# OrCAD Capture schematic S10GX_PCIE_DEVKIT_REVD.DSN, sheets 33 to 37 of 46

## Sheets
33 Power - Select Power Input: size C
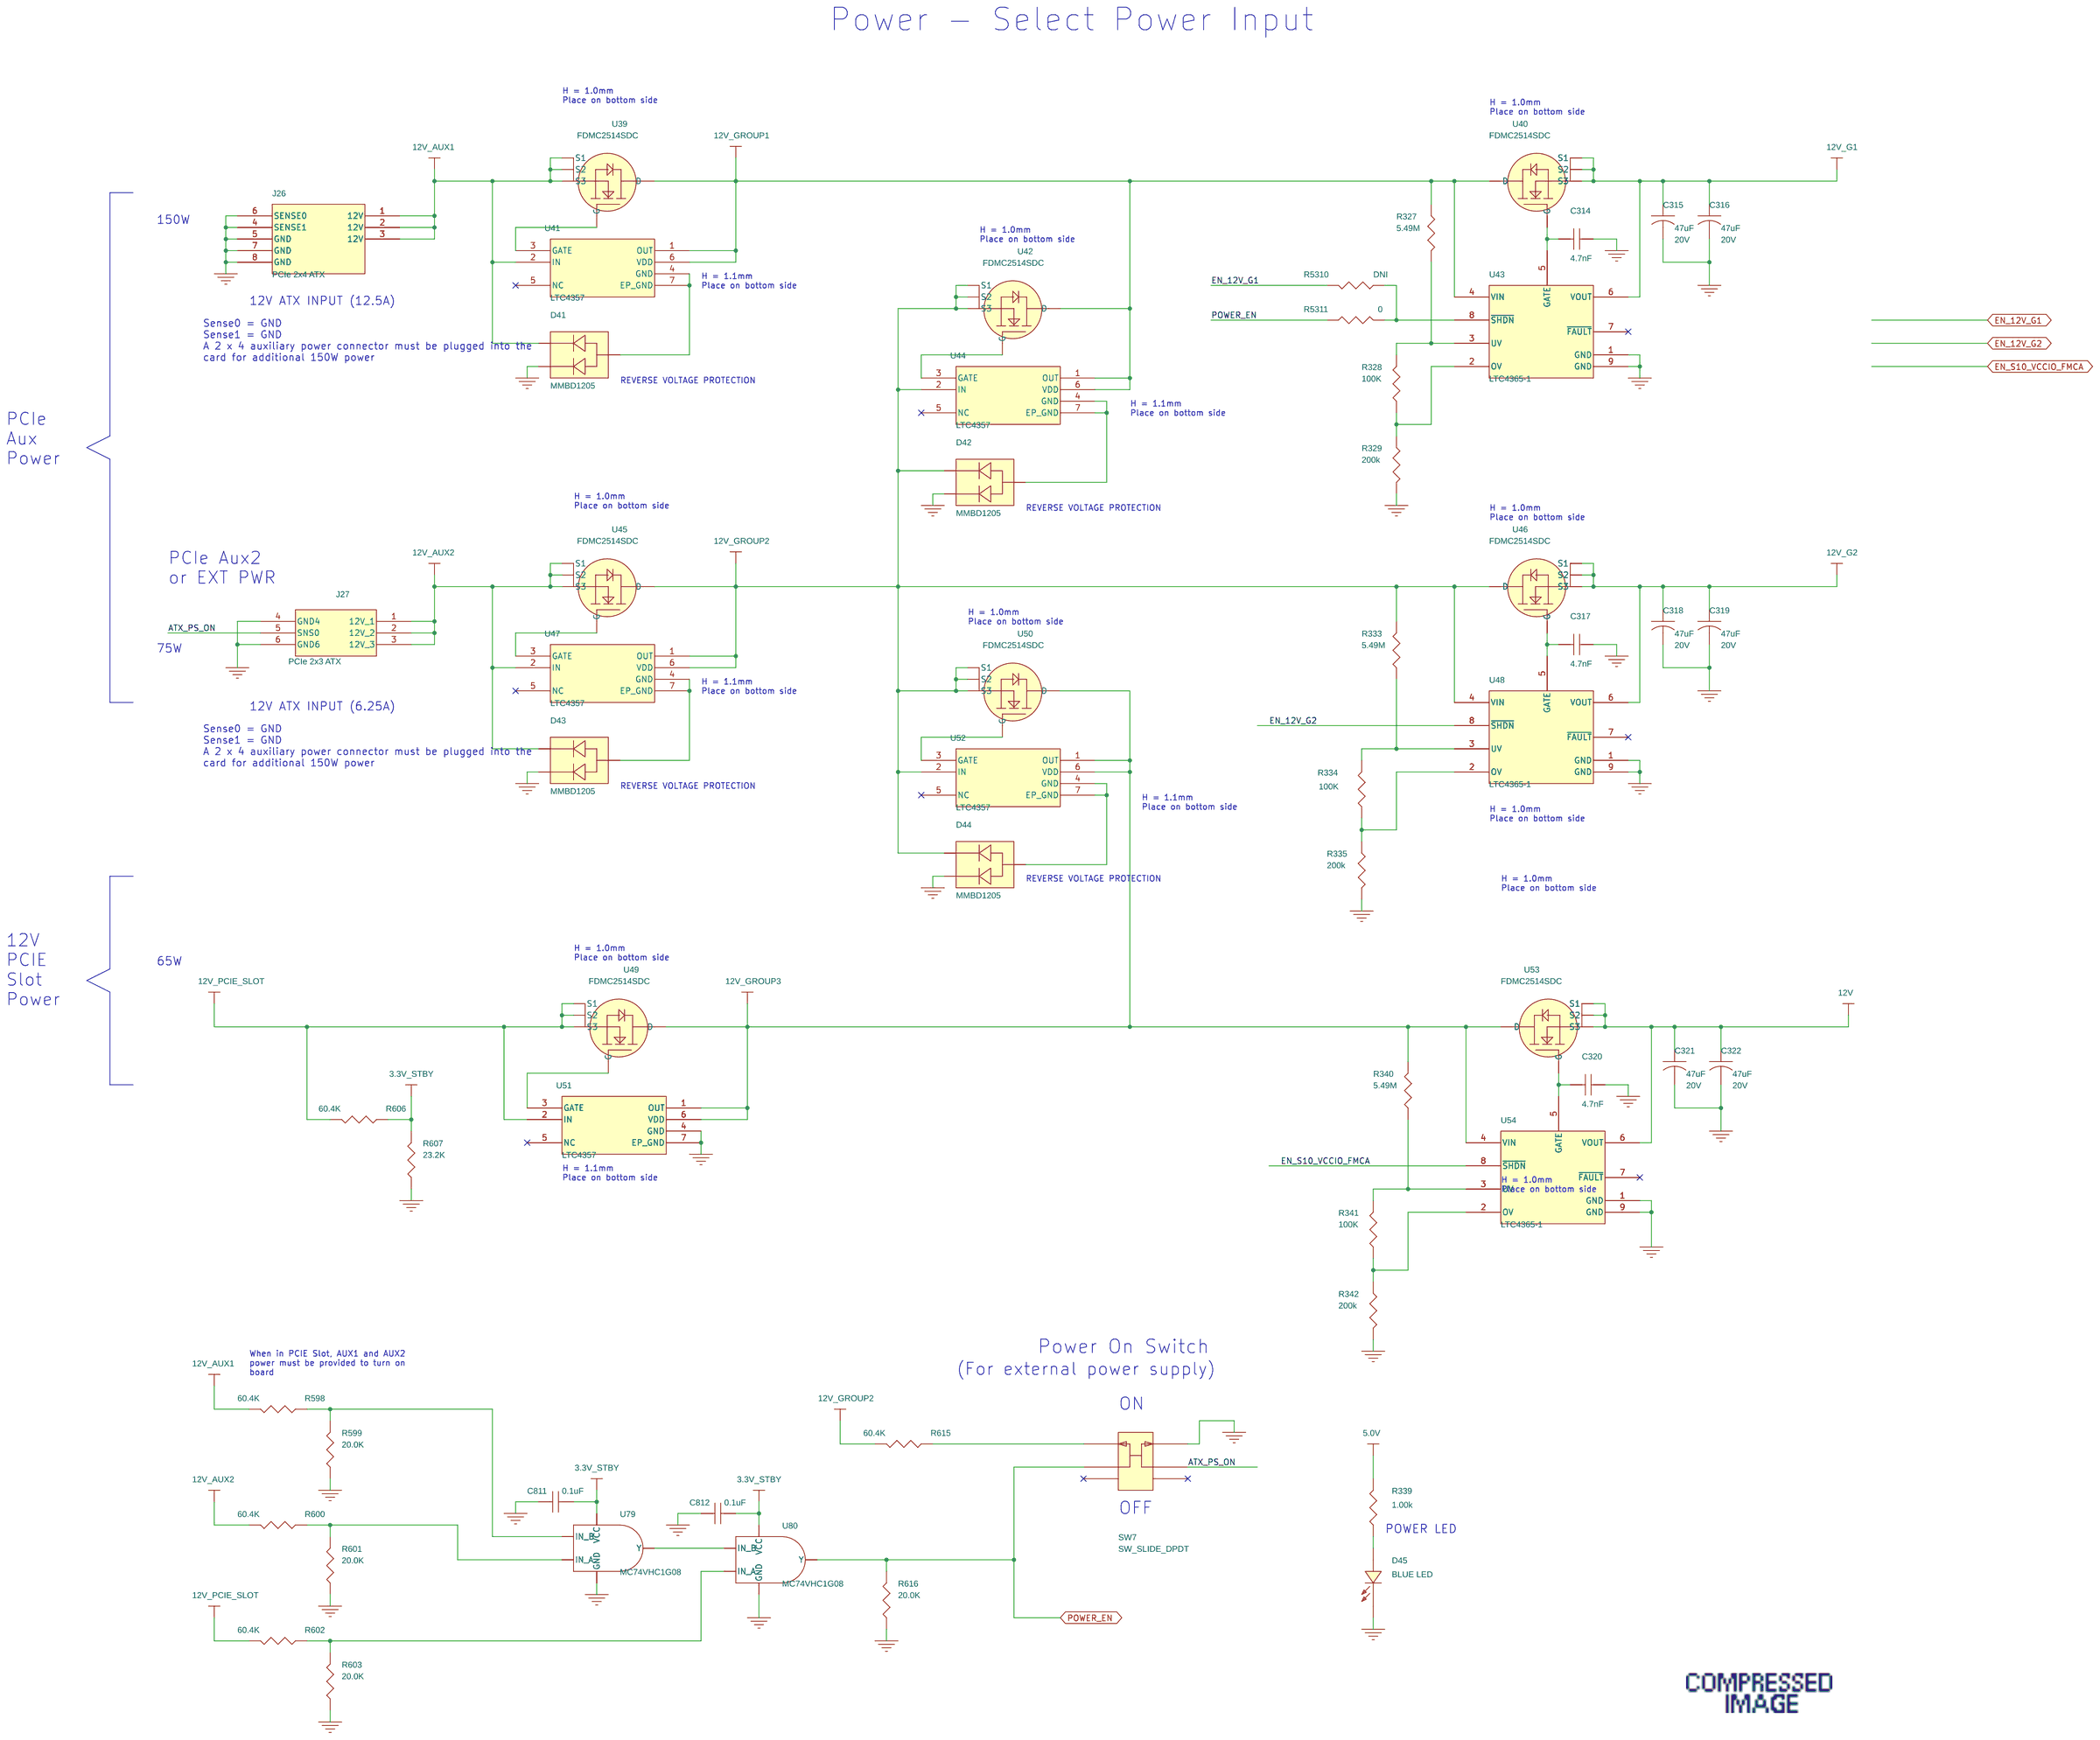
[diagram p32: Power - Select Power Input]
34 Power - 12V-3.3V_REG, 3.3V: size C
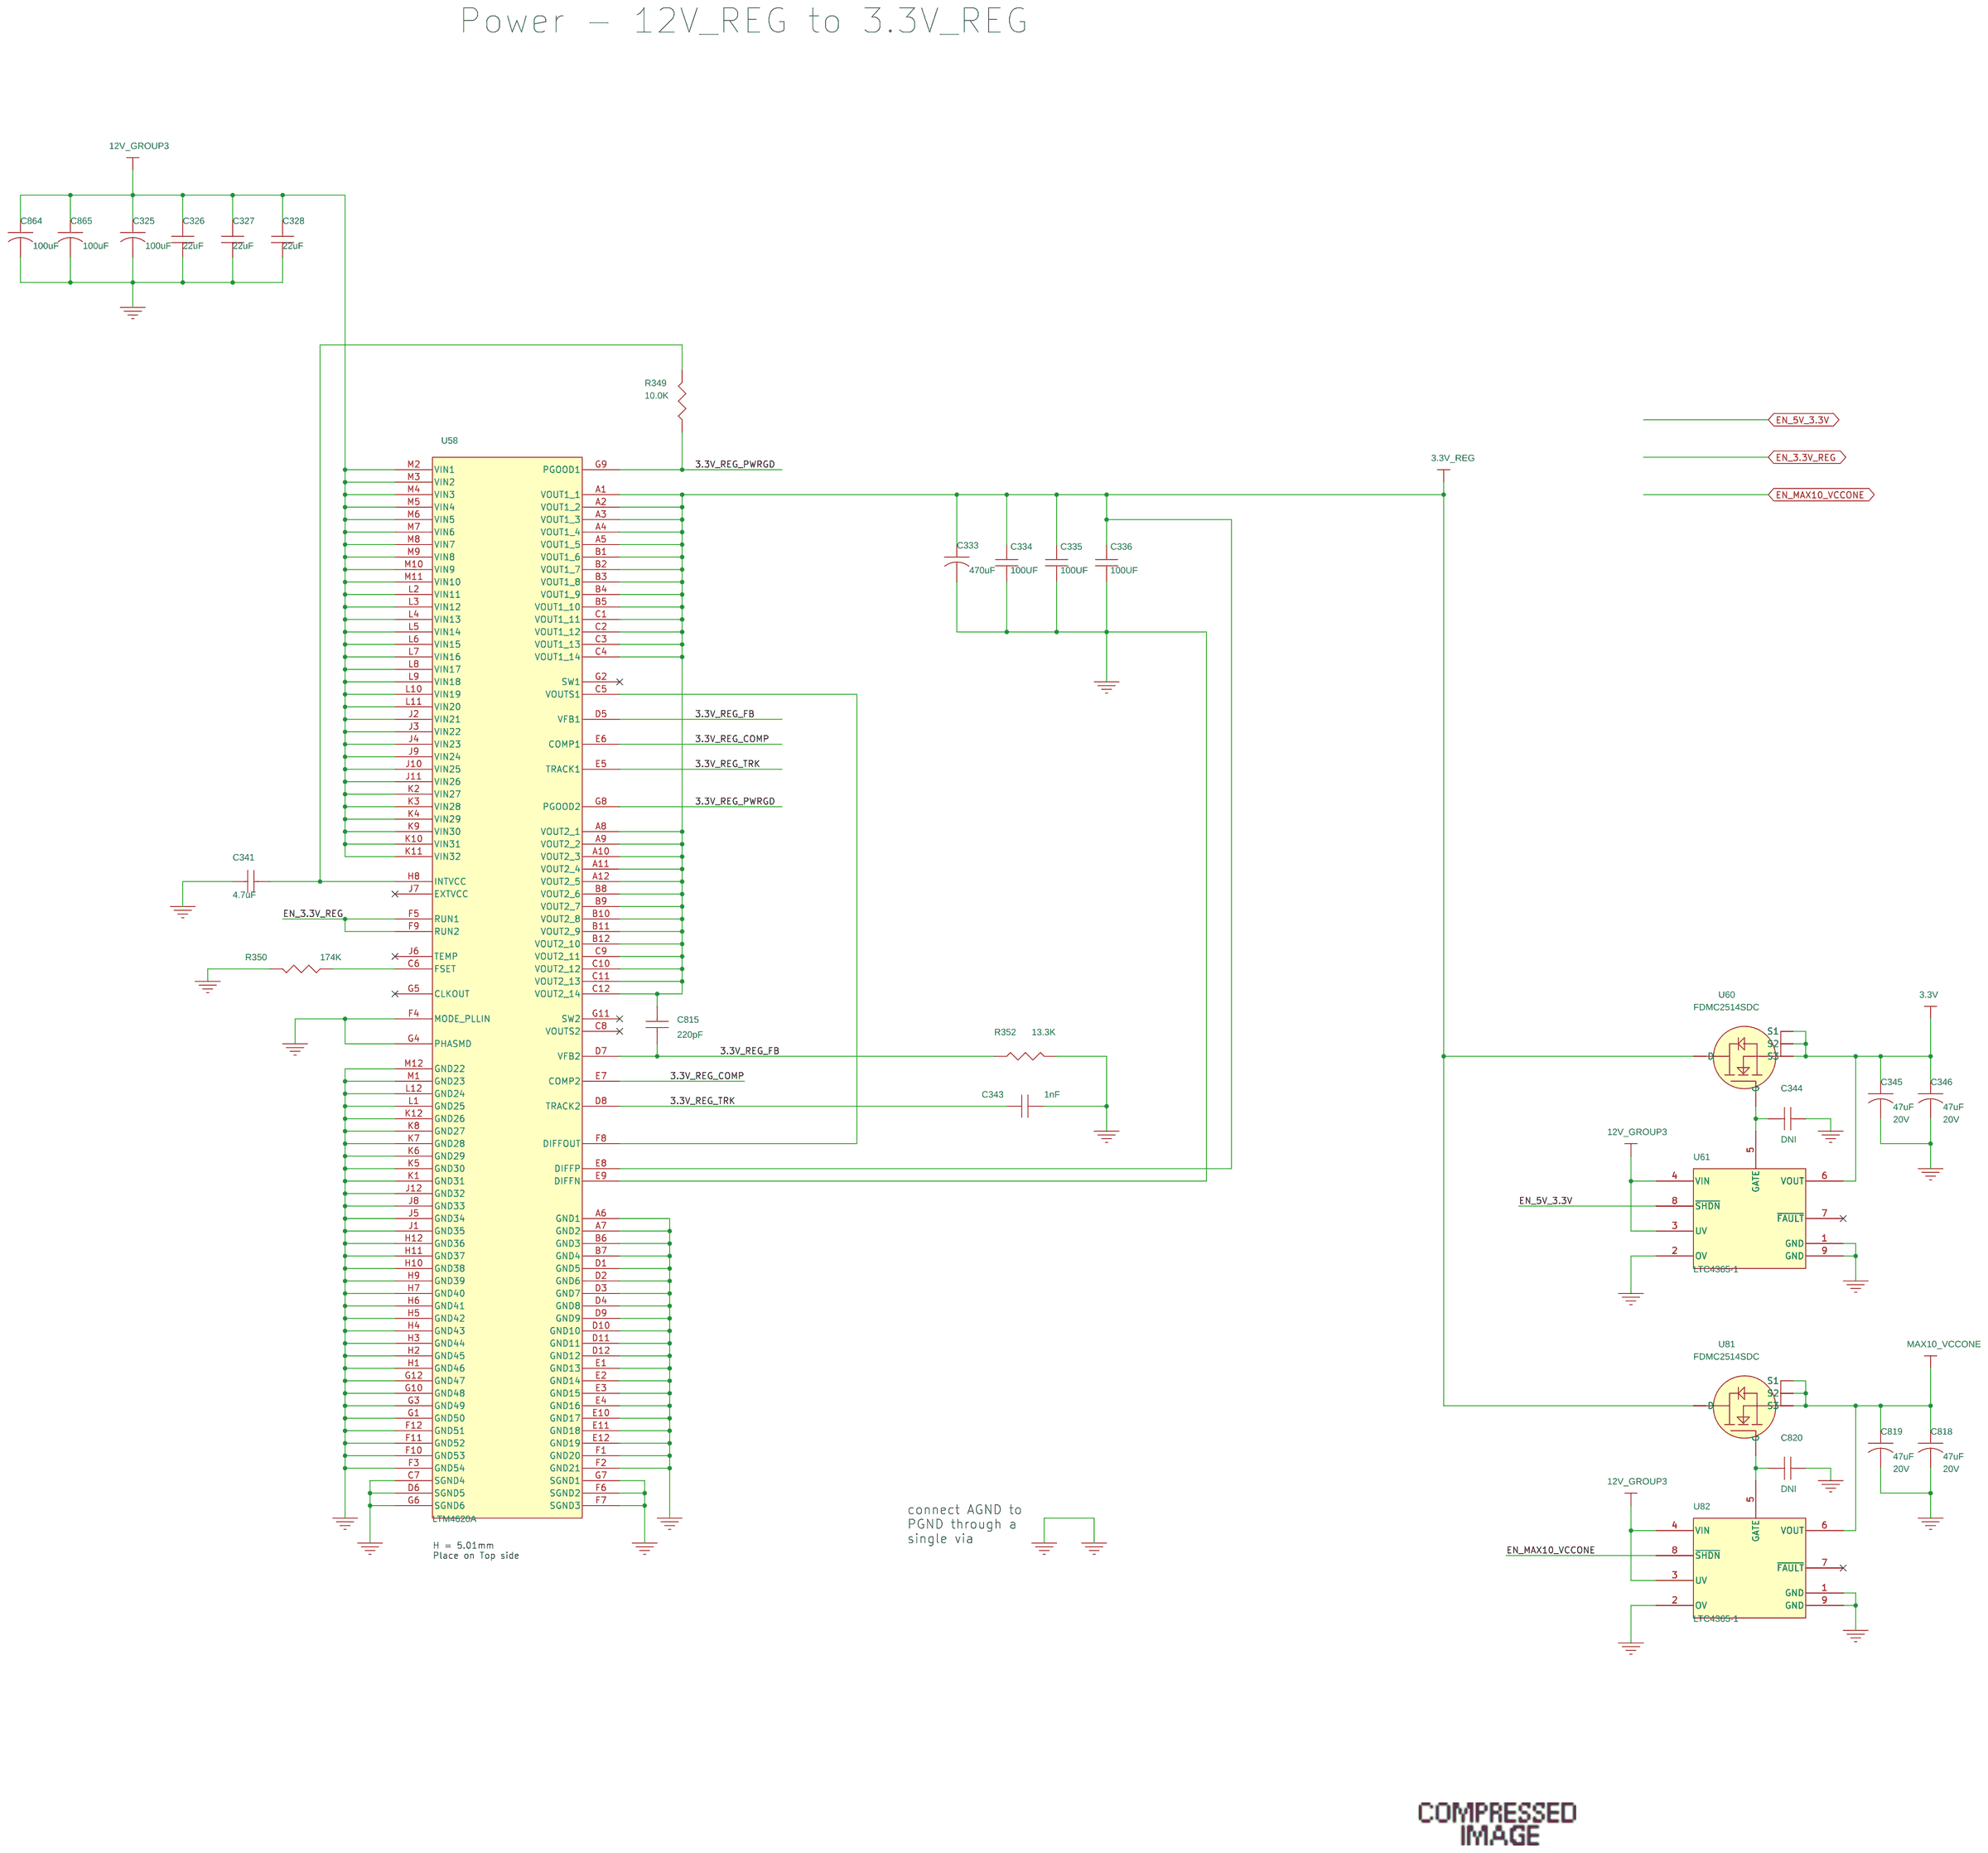
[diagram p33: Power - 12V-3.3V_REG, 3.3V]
35 Power - VCC part 1: size C
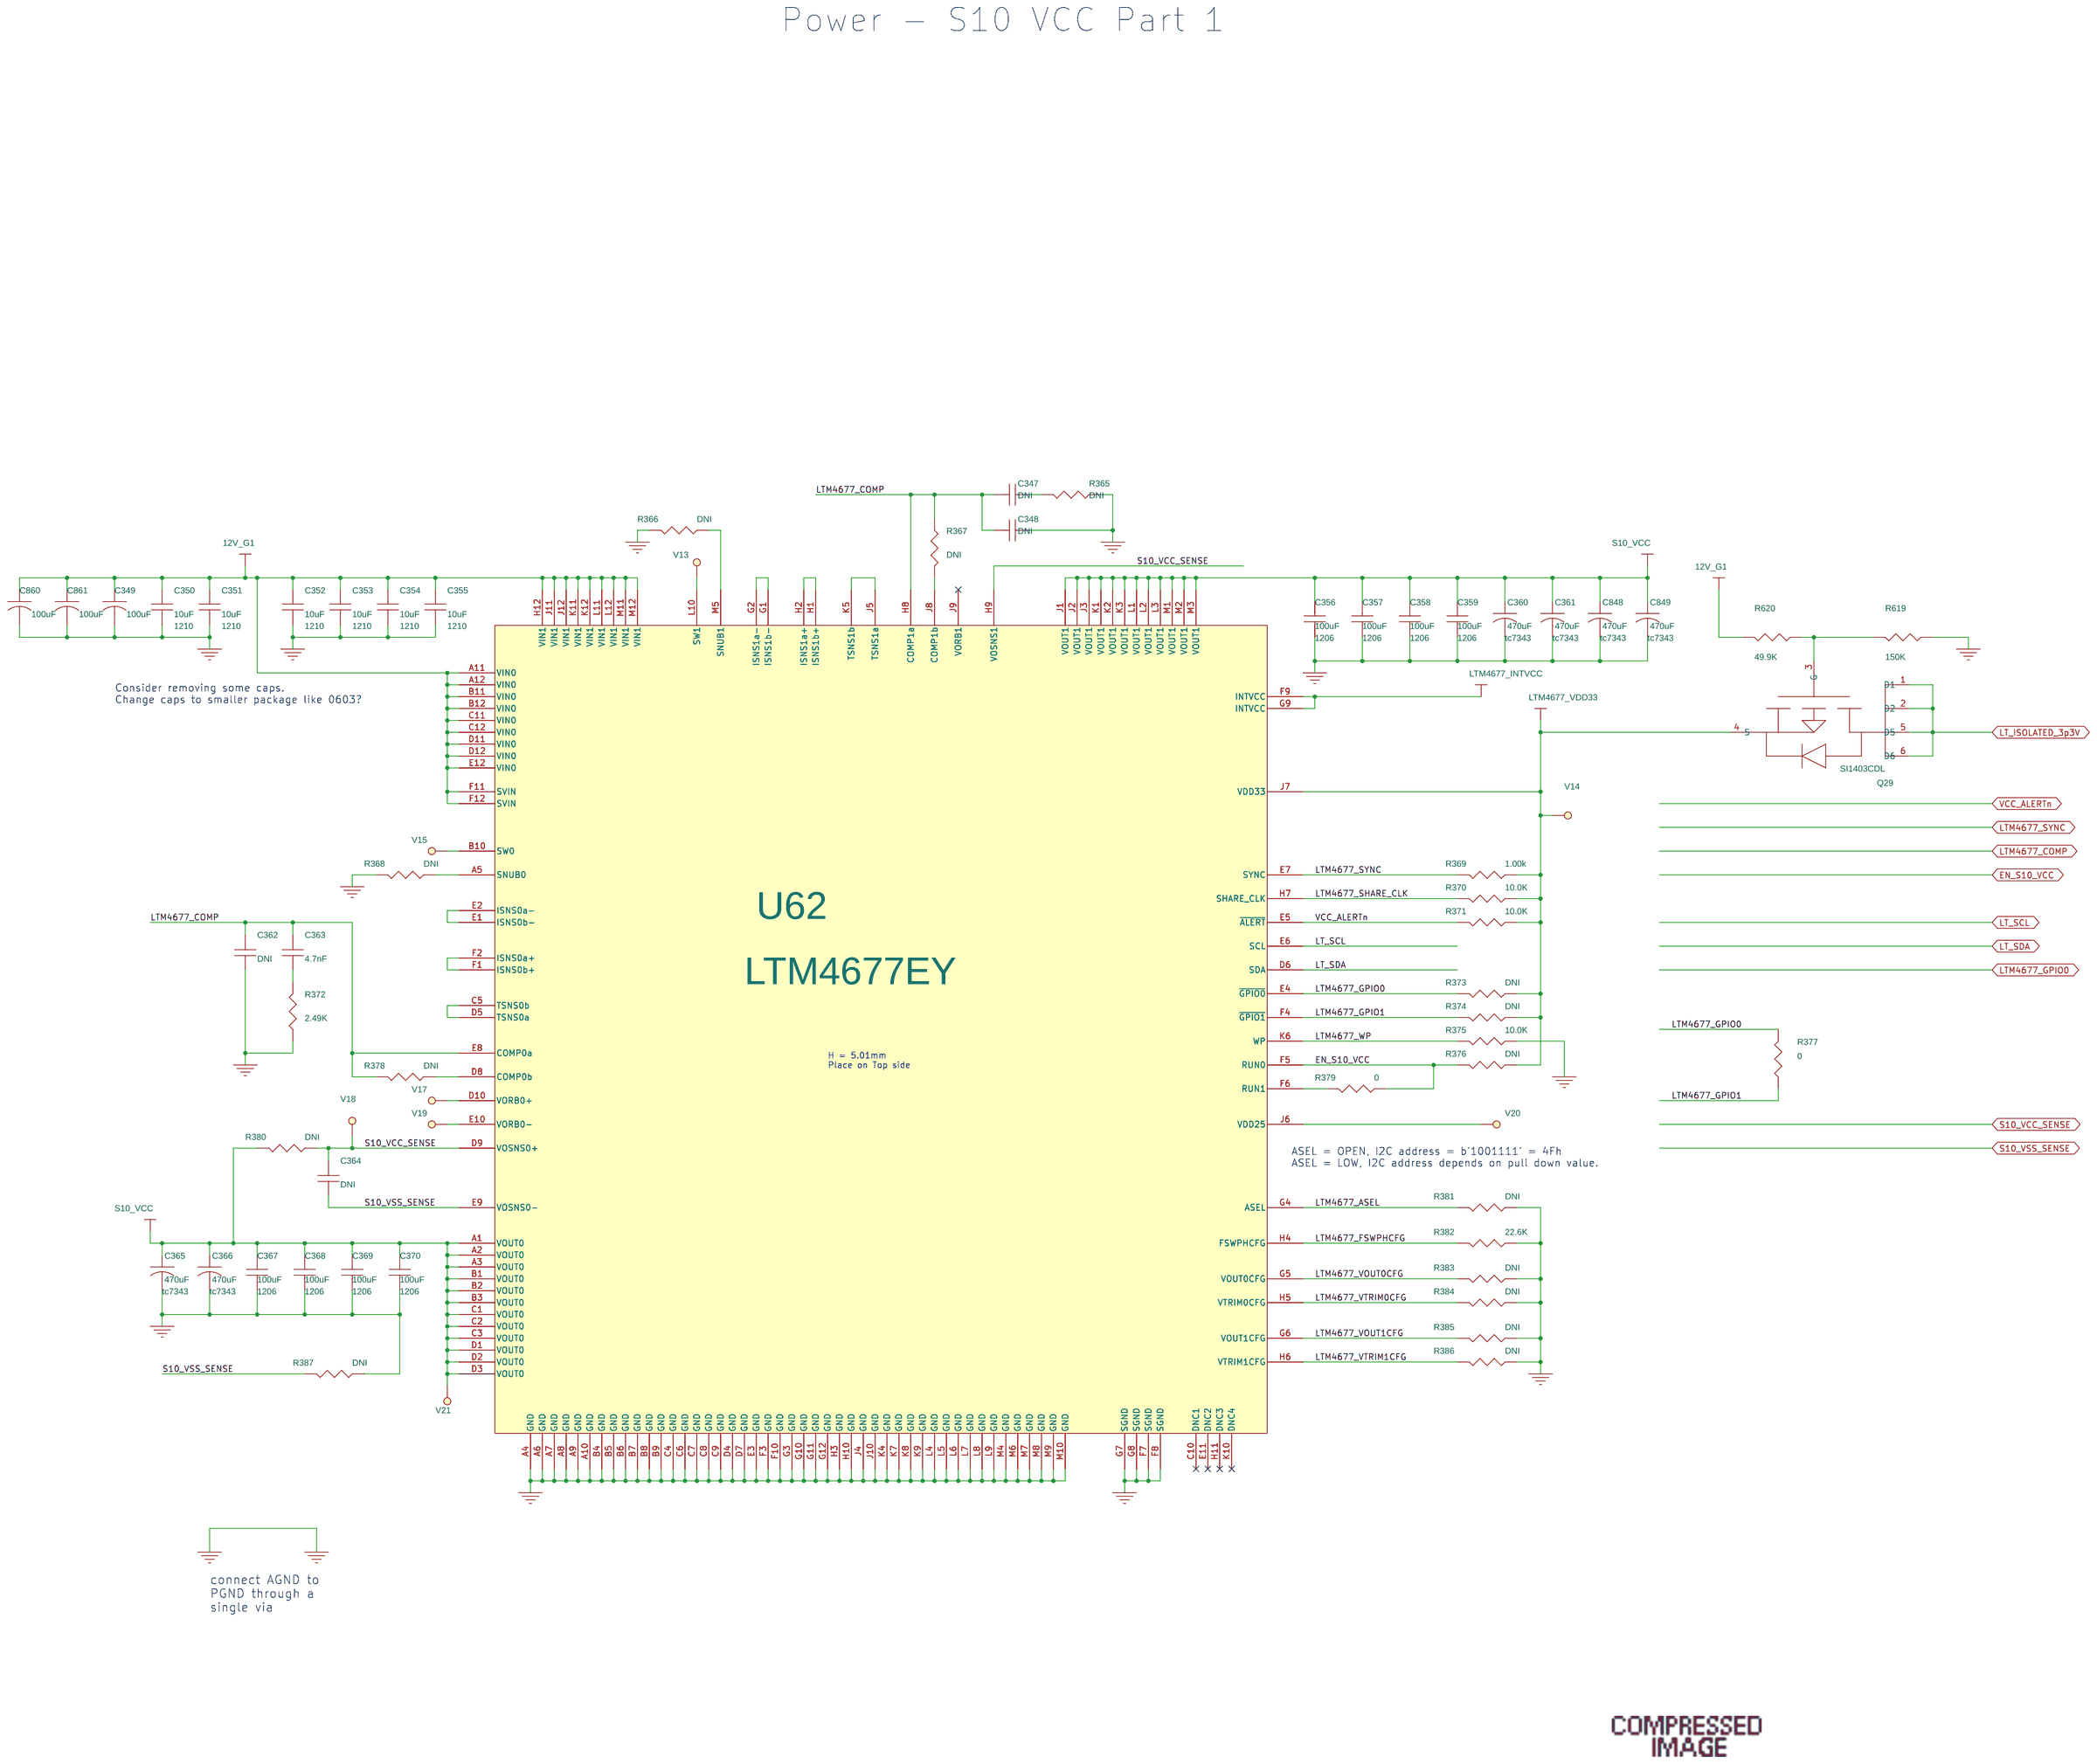
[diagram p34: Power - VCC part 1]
36 Power - VCC part 2: size C
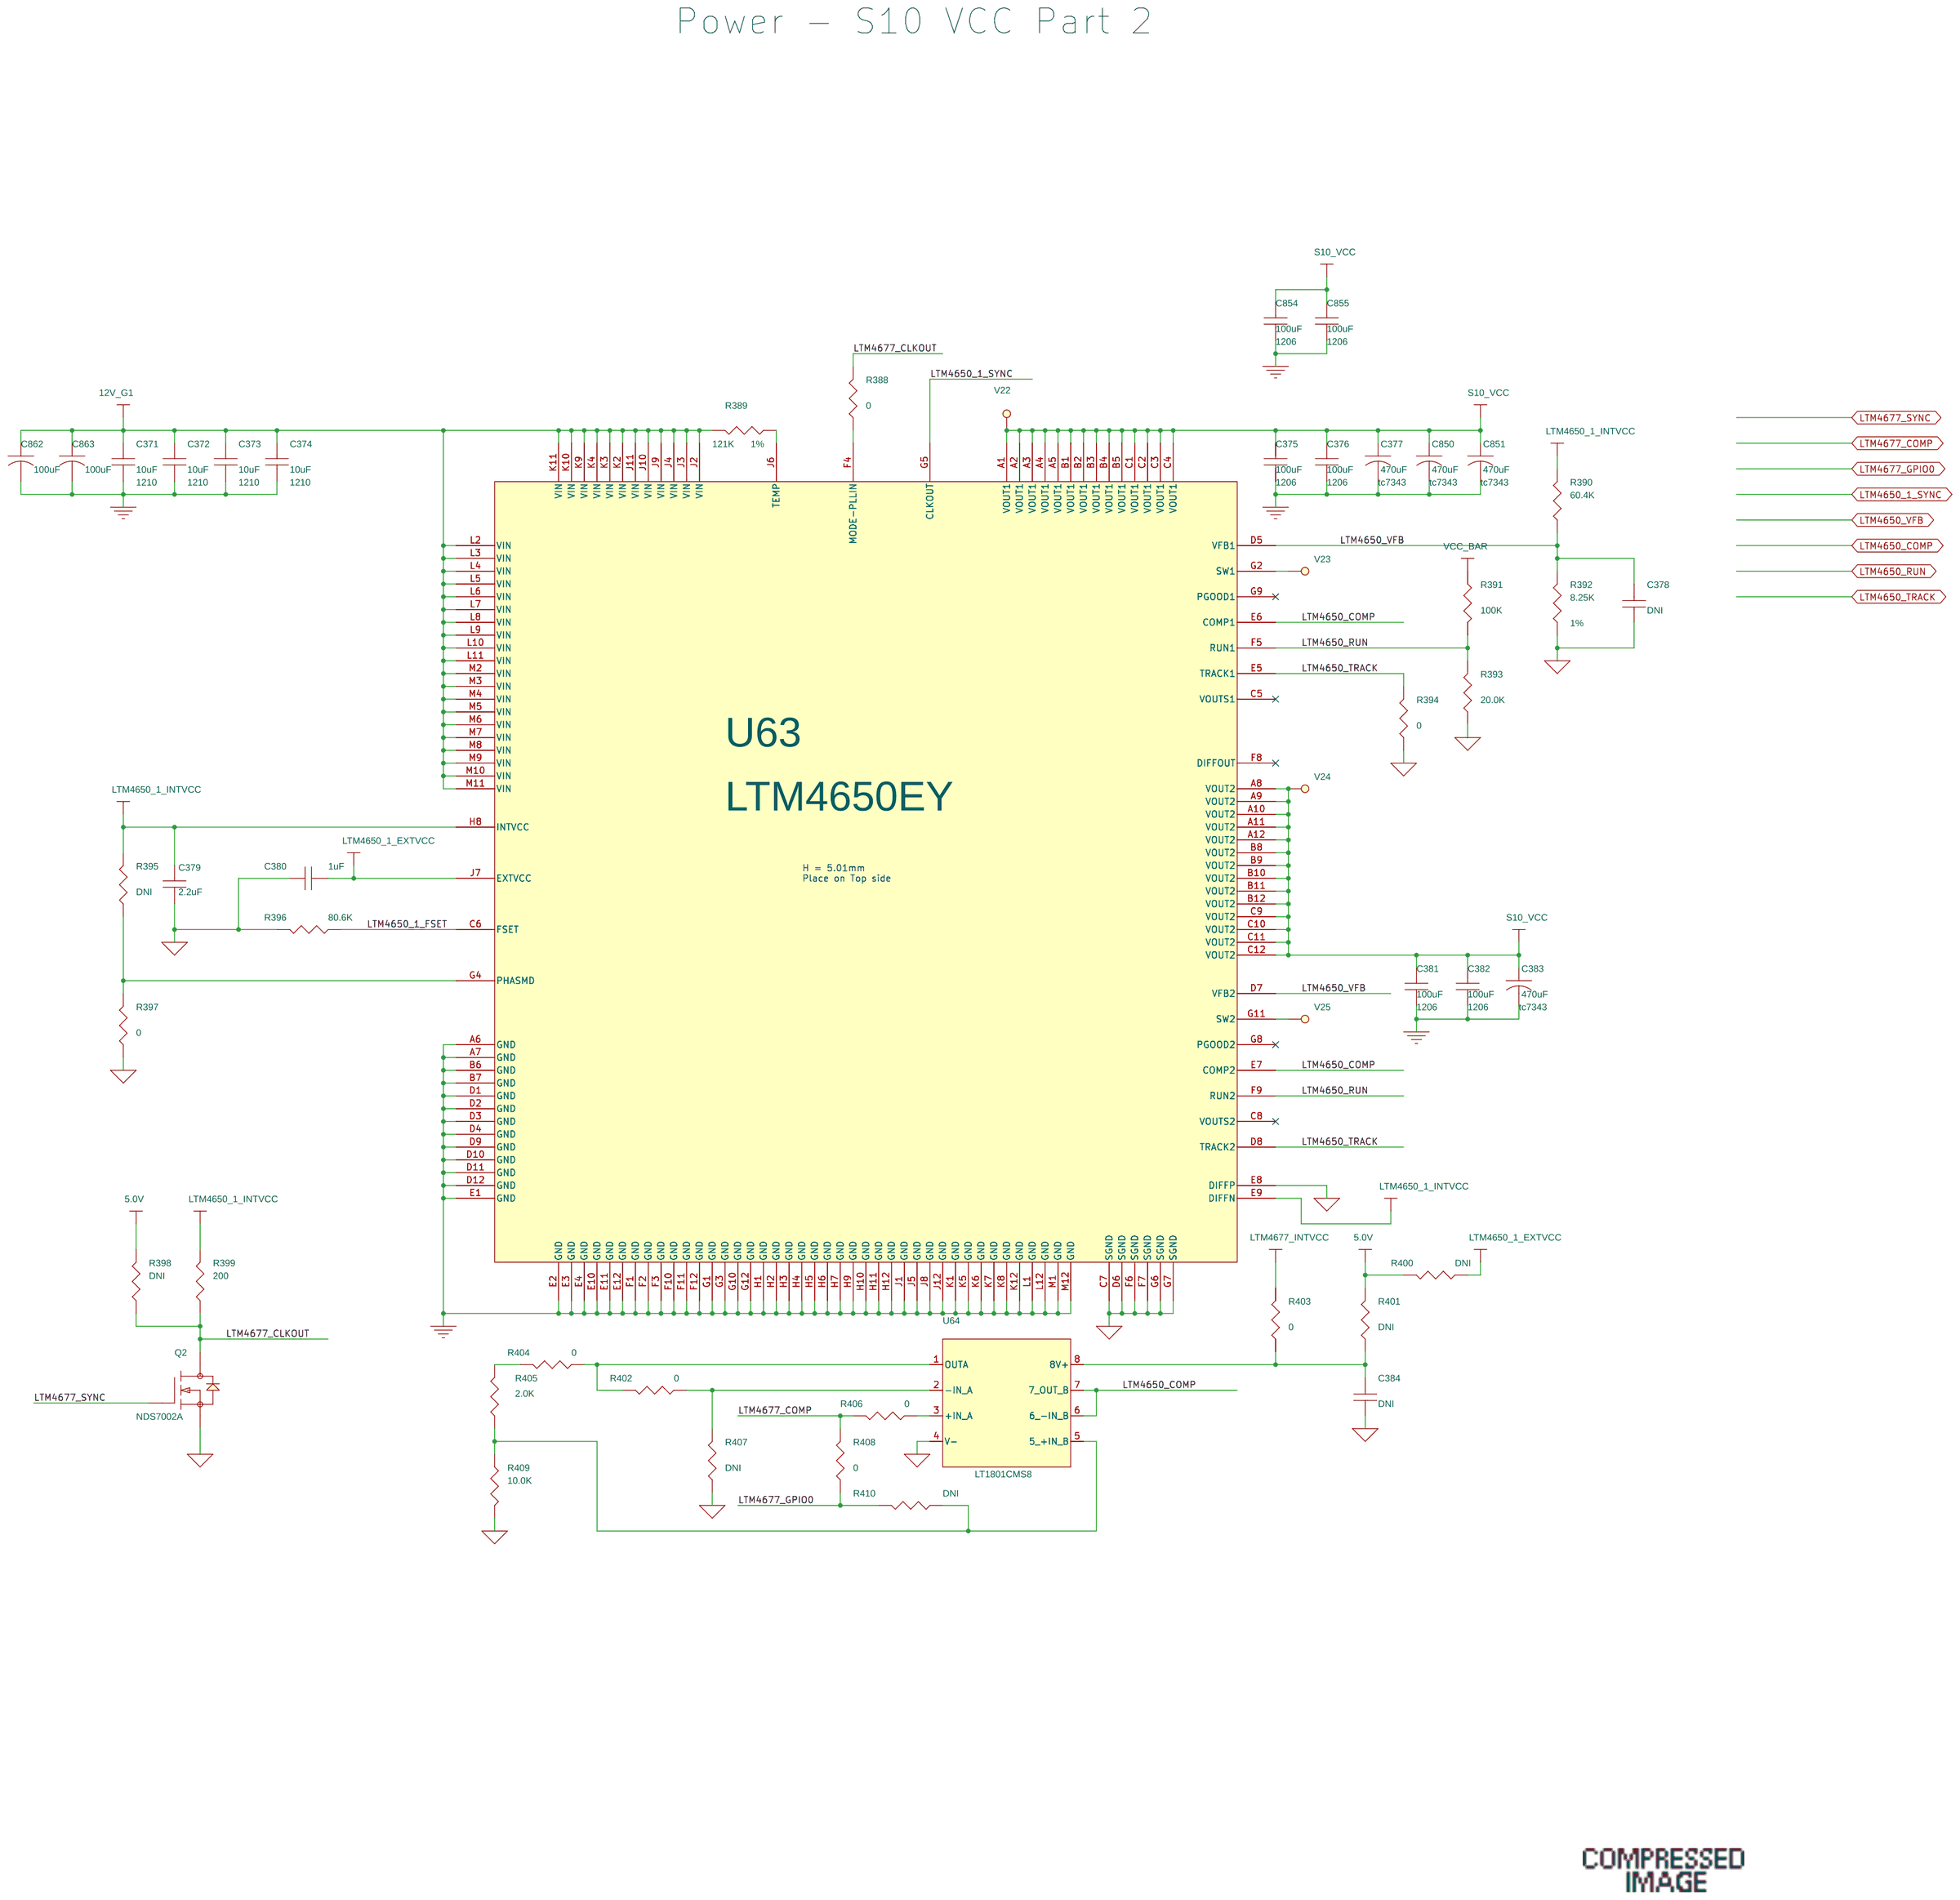
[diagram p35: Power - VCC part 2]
37 Power - VCC part 3: size C
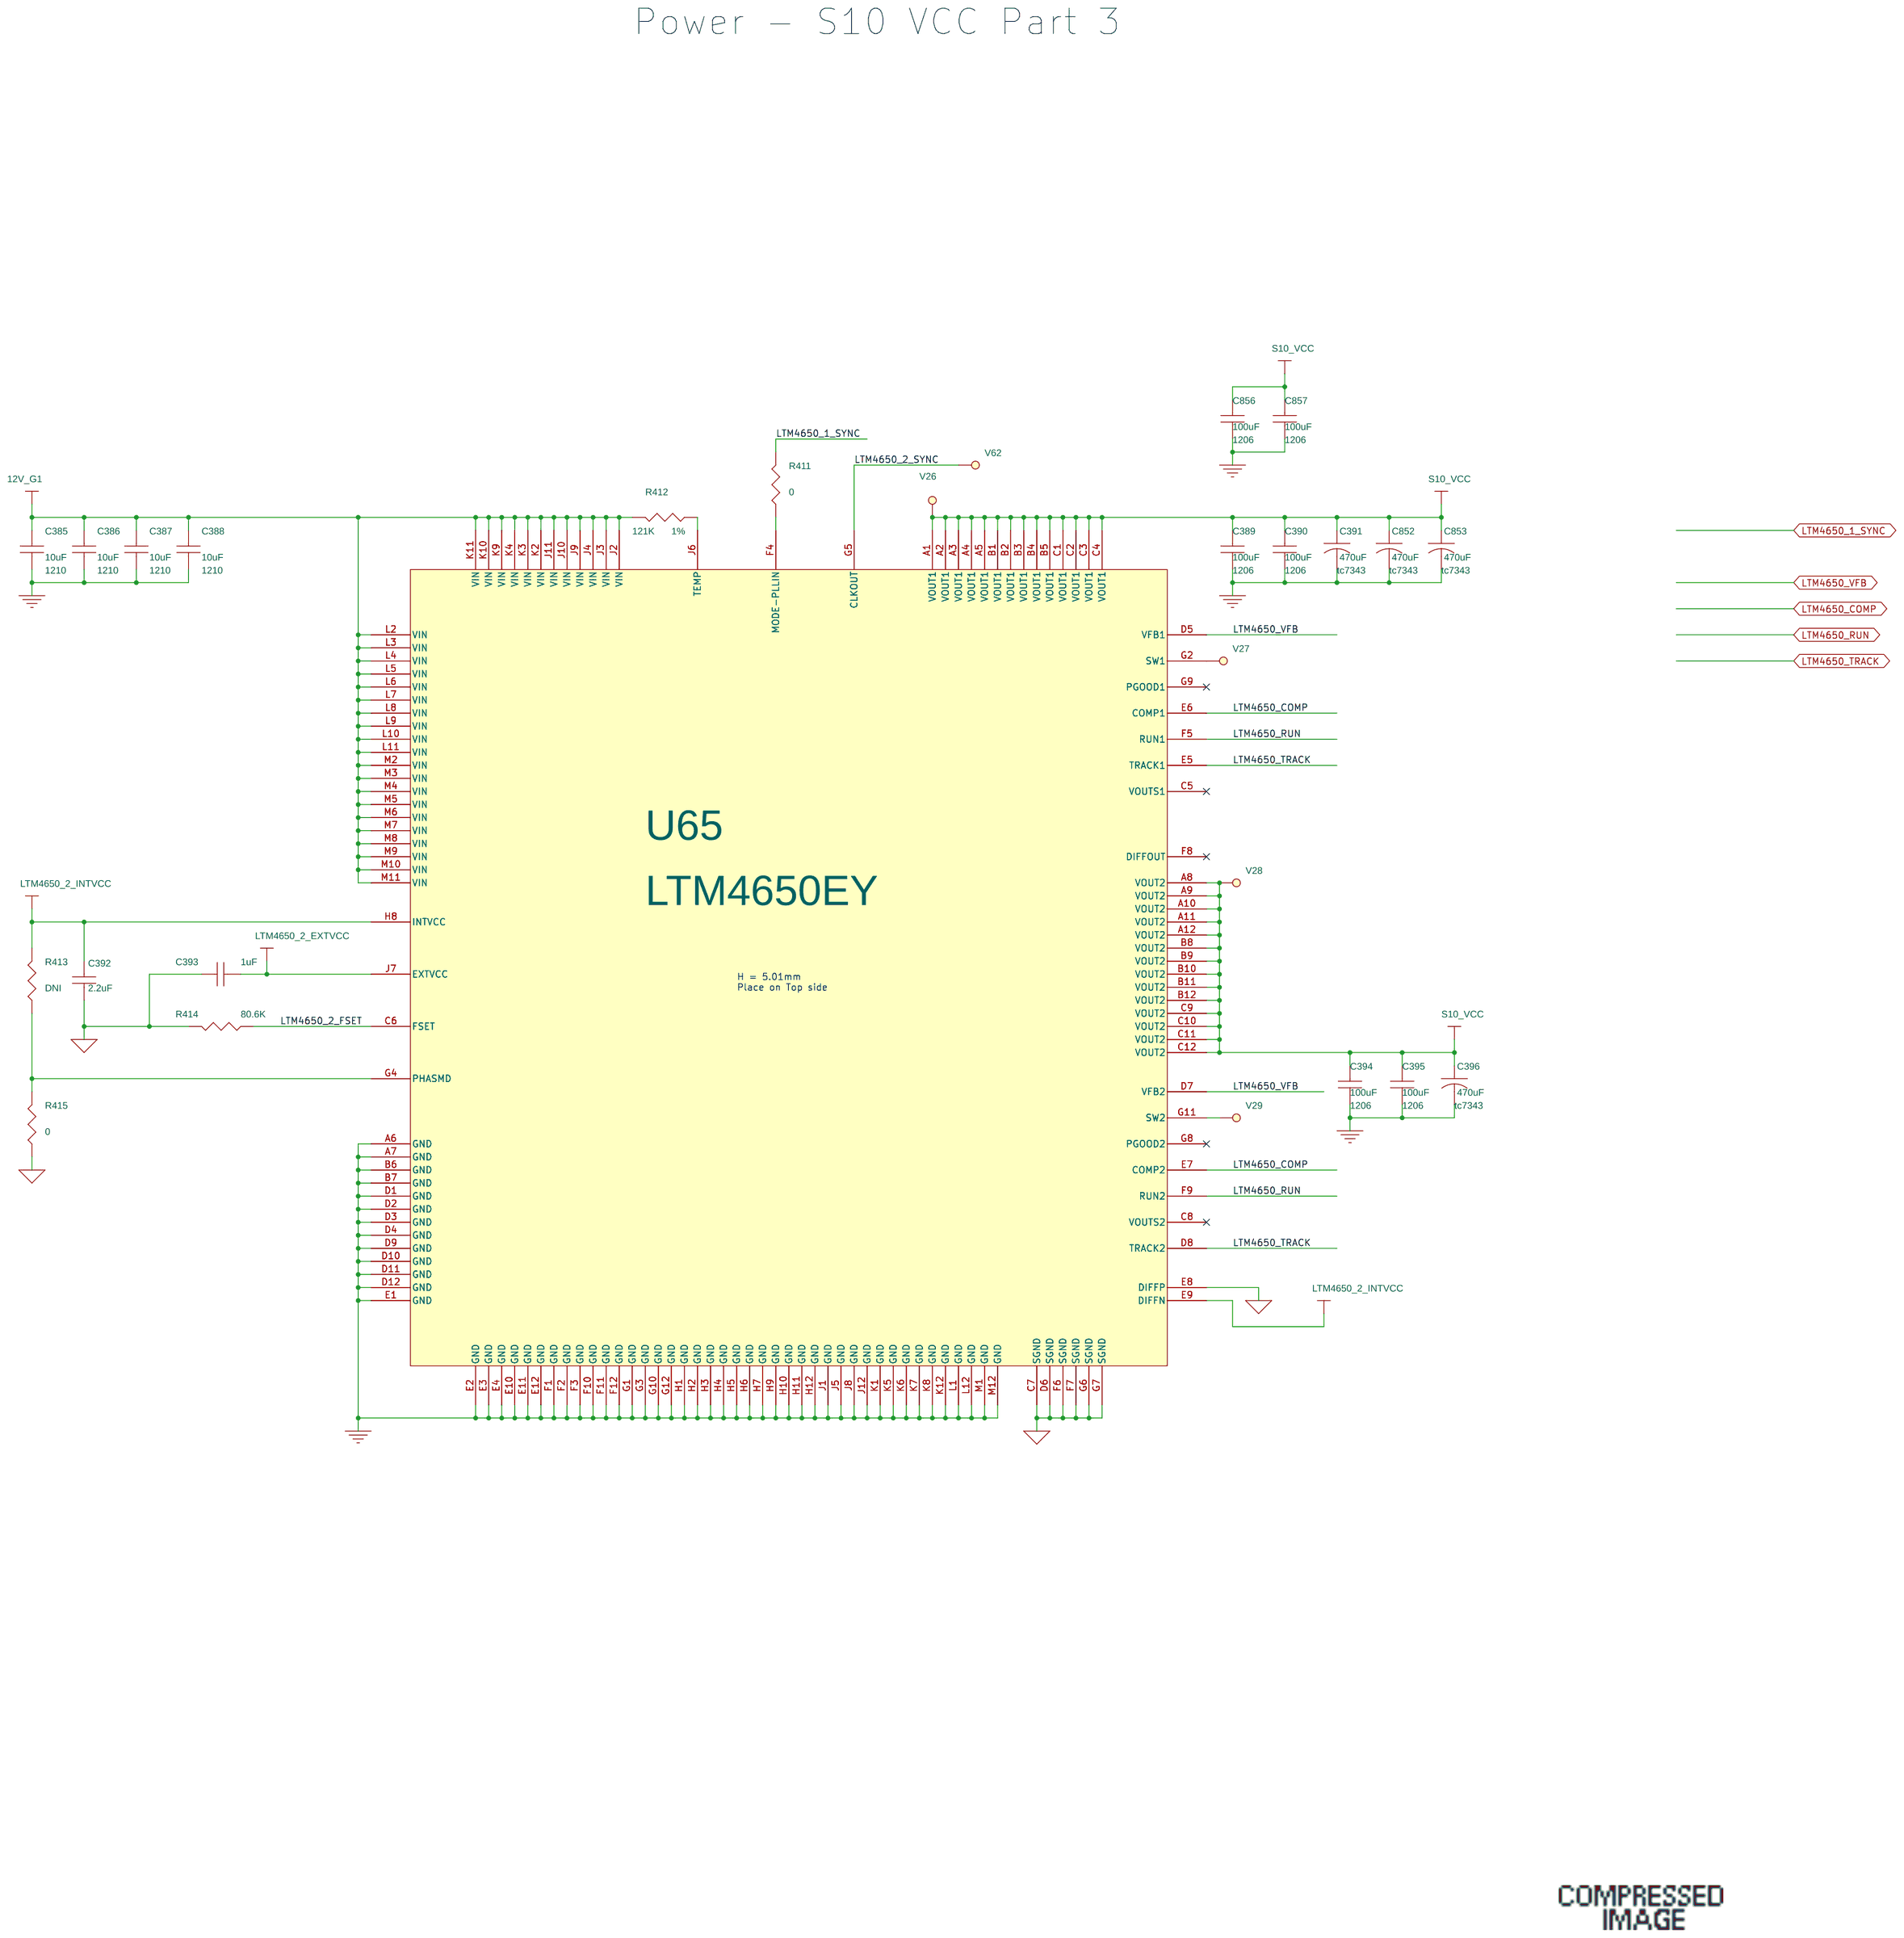
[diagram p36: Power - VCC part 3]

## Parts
sheet Power - 12V-3.3V_REG, 3.3V
C325  100uF  [7343-V_low-profile]
C326  22uF  [1206]
C327  22uF  [1206]
C328  22uF  [1206]
C333  470uF  [7343]
C334  100UF  [1206]
C335  100UF  [1206]
C336  100UF  [1206]
C341  4.7uF  [0402]
C343  1nF  [0402]
C344  DNI  [0402]
C345  47uF  [7343-V_low-profile]
C346  47uF  [7343-V_low-profile]
C815  220pF  [0201]
C818  47uF  [7343-V_low-profile]
C819  47uF  [7343-V_low-profile]
C820  DNI  [0402]
C864  100uF  [7343-V_low-profile]
C865  100uF  [7343-V_low-profile]
R349  10.0K  [0402]
R350  174K  [0402]
R352  13.3K  [0402]
U58  LTM4620A  [BGA-144_REVERSE]
U60  FDMC2514SDC  [FDMC8878_VER2]
U61  LTC4365-1  [DFN8-EPAD_3X2]
U81  FDMC2514SDC  [FDMC8878_VER2]
U82  LTC4365-1  [DFN8-EPAD_3X2]
sheet Power - Select Power Input
C314  4.7nF  [0402]
C315  47uF  [7343-V_low-profile]
C316  47uF  [7343-V_low-profile]
C317  4.7nF  [0402]
C318  47uF  [7343-V_low-profile]
C319  47uF  [7343-V_low-profile]
C320  4.7nF  [0402]
C321  47uF  [7343-V_low-profile]
C322  47uF  [7343-V_low-profile]
C811  0.1uF  [0402]
C812  0.1uF  [0402]
D41  MMBD1205  [SOT23]
D42  MMBD1205  [SOT23]
D43  MMBD1205  [SOT23]
D44  MMBD1205  [SOT23]
D45  BLUE LED  [LUMEX_LED0805]
J26  PCIe 2x4 ATX  [MLX_SD-5569_8POS_RA]
J27  PCIe 2x3 ATX  [PCIe_2x3_ATX]
R327  5.49M  [0402]
R328  100K  [0402]
R329  200k  [0402]
R333  5.49M  [0402]
R334  100K  [0402]
R335  200k  [0402]
R339  1.00k  [0402]
R340  5.49M  [0402]
R341  100K  [0402]
R342  200k  [0402]
R598  60.4K  [0402]
R599  20.0K  [0402]
R600  60.4K  [0402]
R601  20.0K  [0402]
R602  60.4K  [0402]
R603  20.0K  [0402]
R606  60.4K  [0402]
R607  23.2K  [0402]
R615  60.4K  [0402]
R616  20.0K  [0402]
R5310  DNI  [0402]
R5311  0  [0402]
SW7  SW_SLIDE_DPDT  [EG2207]
U39  FDMC2514SDC  [FDMC8878_VER2]
U40  FDMC2514SDC  [FDMC8878_VER2]
U41  LTC4357  [dfn6_epad]
U42  FDMC2514SDC  [FDMC8878_VER2]
U43  LTC4365-1  [DFN8-EPAD_3X2]
U44  LTC4357  [dfn6_epad]
U45  FDMC2514SDC  [FDMC8878_VER2]
U46  FDMC2514SDC  [FDMC8878_VER2]
U47  LTC4357  [dfn6_epad]
U48  LTC4365-1  [DFN8-EPAD_3X2]
U49  FDMC2514SDC  [FDMC8878_VER2]
U50  FDMC2514SDC  [FDMC8878_VER2]
U51  LTC4357  [dfn6_epad]
U52  LTC4357  [dfn6_epad]
U53  FDMC2514SDC  [FDMC8878_VER2]
U54  LTC4365-1  [DFN8-EPAD_3X2]
U79  MC74VHC1G08  [TSOP-5]
U80  MC74VHC1G08  [TSOP-5]
sheet Power - VCC part 1
C347  DNI  [0402]
C348  DNI  [0402]
C349  100uF  [7343-V_low-profile]
C350  10uF  [1210]
C351  10uF  [1210]
C352  10uF  [1210]
C353  10uF  [1210]
C354  10uF  [1210]
C355  10uF  [1210]
C356  100uF  [1206]
C357  100uF  [1206]
C358  100uF  [1206]
C359  100uF  [1206]
C360  470uF  [tc7343]
C361  470uF  [tc7343]
C362  DNI  [0402]
C363  4.7nF  [0402]
C364  DNI  [0402]
C365  470uF  [tc7343]
C366  470uF  [tc7343]
C367  100uF  [1206]
C368  100uF  [1206]
C369  100uF  [1206]
C370  100uF  [1206]
C848  470uF  [tc7343]
C849  470uF  [tc7343]
C860  100uF  [7343-V_low-profile]
C861  100uF  [7343-V_low-profile]
Q29  SI1403CDL  [SOT-363]
R365  DNI  [0402]
R366  DNI  [0402]
R367  DNI  [0402]
R368  DNI  [0402]
R369  1.00k  [0402]
R370  10.0K  [0402]
R371  10.0K  [0402]
R372  2.49K  [0402]
R373  DNI  [0402]
R374  DNI  [0402]
R375  10.0K  [0402]
R376  DNI  [0402]
R377  0  [0402]
R378  DNI  [0402]
R379  0  [0402]
R380  DNI  [0402]
R381  DNI  [0402]
R382  22.6K  [0402]
R383  DNI  [0402]
R384  DNI  [0402]
R385  DNI  [0402]
R386  DNI  [0402]
R387  DNI  [0402]
R619  150K  [0402]
R620  49.9K  [0402]
U62  LTM4677EY  [BGA_144_16x16_1p27]
V13  VIA_1  [TP_020RD_SMT]
V14  VIA_1  [TP_020RD_SMT]
V15  VIA_1  [TP_020RD_SMT]
V17  VIA_1  [TP_020RD_SMT]
V18  VIA_1  [TP_020RD_SMT]
V19  VIA_1  [TP_020RD_SMT]
V20  VIA_1  [TP_020RD_SMT]
V21  VIA_1  [TP_020RD_SMT]
sheet Power - VCC part 2
C371  10uF  [1210]
C372  10uF  [1210]
C373  10uF  [1210]
C374  10uF  [1210]
C375  100uF  [1206]
C376  100uF  [1206]
C377  470uF  [tc7343]
C378  DNI  [0402]
C379  2.2uF  [0603]
C380  1uF  [C0402-8]
C381  100uF  [1206]
C382  100uF  [1206]
C383  470uF  [tc7343]
C384  DNI  [0402]
C850  470uF  [tc7343]
C851  470uF  [tc7343]
C854  100uF  [1206]
C855  100uF  [1206]
C862  100uF  [7343-V_low-profile]
C863  100uF  [7343-V_low-profile]
Q2  NDS7002A  [SOT23]
R388  0  [0402]
R389  121K  [0402]
R390  60.4K  [0402]
R391  100K  [0402]
R392  8.25K  [0402]
R393  20.0K  [0402]
R394  0  [0402]
R395  DNI  [0402]
R396  80.6K  [0402]
R397  0  [0402]
R398  DNI  [0402]
R399  200  [0402]
R400  DNI  [0402]
R401  DNI  [0402]
R402  0  [0402]
R403  0  [0402]
R404  0  [0402]
R405  2.0K  [0402]
R406  0  [0402]
R407  DNI  [0402]
R408  0  [0402]
R409  10.0K  [0402]
R410  DNI  [0402]
U63  Volt. Reg.  [BGA-144_REVERSE]
U64  LT1801CMS8  [MSOP-8]
V22  VIA_1  [TP_020RD_SMT]
V23  VIA_1  [TP_020RD_SMT]
V24  VIA_1  [TP_020RD_SMT]
V25  VIA_1  [TP_020RD_SMT]
sheet Power - VCC part 3
C385  10uF  [1210]
C386  10uF  [1210]
C387  10uF  [1210]
C388  10uF  [1210]
C389  100uF  [1206]
C390  100uF  [1206]
C391  470uF  [tc7343]
C392  2.2uF  [0603]
C393  1uF  [C0402-8]
C394  100uF  [1206]
C395  100uF  [1206]
C396  470uF  [tc7343]
C852  470uF  [tc7343]
C853  470uF  [tc7343]
C856  100uF  [1206]
C857  100uF  [1206]
R411  0  [0402]
R412  121K  [0402]
R413  DNI  [0402]
R414  80.6K  [0402]
R415  0  [0402]
U65  Volt. Reg.  [BGA-144_REVERSE]
V26  VIA_1  [TP_020RD_SMT]
V27  VIA_1  [TP_020RD_SMT]
V28  VIA_1  [TP_020RD_SMT]
V29  VIA_1  [TP_020RD_SMT]
V62  VIA_1  [TP_020RD_SMT]

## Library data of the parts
C325 C349 C860-C865 = PCAP: CAP TANT POLY 100UF 16V 2917; Item Num: P03-17867R; LIFECYCLE_PHASE: Active; Lead Free Status: Lead Free; MFR_LIFECYCLE: Active; Manufacturer: Panasonic; Manufacturer Part Num: 16TQC100MYF; Num Pins: 2; PART_SUBCLASS: CAPACITORS; RoHS Compliant: RoHS Compliant; TOLERANCE: +/-20%; Working Voltage: 16V
C326-C328 = CAP: CAP - CER, 22UF, 25V, 10%, X5R, 1206; Item Num: P03-17640R; Lead Free Status: Yes; Manufacturer: Murata; Manufacturer Part Num: GRM31CR61E226KE15L; Num Pins: 2; Part Class: Capacitors; Price: 0; RoHS Compliant: Yes
C333 = PCAP: CAP TANT 470UF 6.3V 20% SMD, T530 POLYMER TANTALUM KO-CAP, LOW ESR 5 MOHM; Item Num: P03-17578R; LIFECYCLE_PHASE: Active; Lead Free Status: Lead Free; MFR_LIFECYCLE: Active; Manufacturer: Kemet; Manufacturer Part Num: T530Y477M006ATE005; Num Pins: 2; PART_SUBCLASS: CAPACITORS; RoHS Compliant: RoHS Compliant; TOLERANCE: +/-20%; Working Voltage: 6.3V
C334-C336 = CAP: CAP -   CER, 100UF, 10V, 20%, X5R, 1206, HIEGHT 1.6mm; AGILE_LINK: http://sj-agile9app/Agile/PLMServlet?action=OpenEmailObject&classid=10000&objid=146494148; CAPACITANCE: 47uF; Item Num: P03-17591R; LIFECYCLE_PHASE: Active; MFR_LIFECYCLE: Active; Manufacturer: TDK Electronics; Manufacturer Part Num: C3216X51A107M; Num Pins: 2; PART_SUBCLASS: CAPACITORS; RATED_VOLTAGE: 10V; RoHS Compliant: RoHS Compliant; TOLERANCE: 20%
C341 = CAP: CAP - CERAMIC, 4.7UF, 6.3V, 10%, X5R, 0402; AGILE_LINK: http://sj-agile9app/Agile/PLMServlet?action=OpenEmailObject&classid=10000&objid=257560276; Item Num: P03-17432R; LIFECYCLE_PHASE: Active; Lead Free Status: Not Lead Free; MFR_LIFECYCLE: Active; Manufacturer: Murata; Manufacturer Part Num: GRM155R60J475ME87D; Num Pins: 2; PART_SUBCLASS: CAPACITORS; RATED_VOLTAGE: 6.3V; RoHS Compliant: RoHS Compliant; TOLERANCE: +/-10%
C343 = CAP: CAP - CER 1NF 50V C0G 0402; Item Num: P03-15273R; Lead Free Status: Yes; Manufacturer: Murata; Manufacturer Part Num: GRM1555C1H102JA01D; Num Pins: 2; Part Class: Capacitors; Price: 0; RoHS Compliant: Yes
C314 C317 C320 C344 C820 = CAP: CAP CER 4700PF 50V 10% X7R 0402; AGILE_LINK: http://sj-agile9app/Agile/PLMServlet?action=OpenEmailObject&classid=10000&objid=256989767; CAPACITANCE: 15000pF; Item Num: P03-17789R; LIFECYCLE_PHASE: Active; Lead Free Status: Lead Free; MFR_LIFECYCLE: Active; Manufacturer: Murata; Manufacturer Part Num: GRM155R71H472KA01J; Num Pins: 2; PART_SUBCLASS: CAPACITORS; RATED_VOLTAGE: 50V; RoHS Compliant: RoHS Compliant; TOLERANCE: 10%
C315 C316 C318 C319 C321 C322 C345 C346 C818 C819 = PCAP: CAP - TANT POLY, 47UF, 20%, 20V, 90mOhm SER, SMD Low-profile (1.9mm); Item Num: P03-17452R; LIFECYCLE_PHASE: Active; Lead Free Status: Lead Free; MFR_LIFECYCLE: Active; Manufacturer: Kemet; Manufacturer Part Num: T521V476M020ATE090; Num Pins: 2; PART_SUBCLASS: CAPACITORS; RATED_VOLTAGE: 20V; RoHS Compliant: RoHS Compliant; TOLERANCE: +/-20%; Working Voltage: 20V
C815 = CAP: CAP - CER, 0.22UF, 10V, 10%, X5R, 0201; AGILE_LINK: http://sj-agile9app/Agile/PLMServlet?action=OpenEmailObject&classid=10000&objid=257560276; CAPACITANCE: 0.22uF; Item Num: P03-17863R; LIFECYCLE_PHASE: Active; Lead Free Status: Lead Free; MFR_LIFECYCLE: Active; Manufacturer: Murata; Manufacturer Part Num: GRM033R71E221KA01D; Num Pins: 2; PART_SUBCLASS: CAPACITORS; RATED_VOLTAGE: 10V; RoHS Compliant: RoHS Compliant
R349 R409 = RESISTOR: RES,10.0K OHMS,1.0%,1/16W, 0402; AGILE_LINK: http://sj-agile9app/Agile/PLMServlet?action=OpenEmailObject&classid=10000&objid=146548997; Item Num: P02-11364R; LIFECYCLE_PHASE: Active; Lead Free Status: No; MFR_LIFECYCLE: Active; Manufacturer: Panasonic; Manufacturer Part Num: ERJ-2RKF1002X; Num Pins: 2; PART_SUBCLASS: RESISTORS; POWER: 1/16W; RESISTANCE: 10K; RoHS Compliant: Yes; TOLERANCE: +/-1%
R350 = RESISTOR_0402: RES - 174K OHM, 1%, 1/16W, 0402; Manufacturer: Panasonic; Manufacturer Part Num: ERJ-2RKF1743X; Manufacturer Part Number: ERJ-2RKF1743X; item Num: P02-17501R
R352 = RESISTOR: RES - 13.3K OHM, 1/16W, 1%, 0402 SMD; Item Num: P02-14487R; Lead Free Status: Yes; Manufacturer: Vishay; Manufacturer Part Num: CRCW040213K3FKED; Num Pins: 2; Part Class: RESISTORS; Price: 0; RoHS Compliant: Yes
U58 = LTM4630A: IC, Dual 13A or Single 26A DC/DC Umodule Regulator; Item Num: P05-18752R; Manufacturer: Linear Technology; Manufacturer Part Num: LTM4620AEY#PBF
U39 U40 U42 U45 U46 U49 U50 U53 U60 U81 = FDMC8878_VER2: MOSFET N-CHANNEL DUAL COOL PWR TRENCH 40A 25V 3.5mOHM; Item Num: P18-31451R; Manufacturer: Fairchild Semiconductor; Manufacturer Part Num: FDMC25214SDC
U43 U48 U54 U61 U82 = LTC4365_DFN: IC - LT4365-1, DFN8, UV, OV, REVERSE SUPPLY PROTECTION, VIN=2.5V-34V, (3 X 2 X 0.75)MM, TEMP=-40C-125C; Item Num: P01-17989R; LIFECYCLE_PHASE: Active; Lead Free Status: Lead Free; MFR_LIFECYCLE: Active; Manufacturer: Linear Technology; Manufacturer Part Num: LTC4365HDDB-1#TRMPBF; Num Pins: 9; PART_SUBCLASS: ICS; RoHS Compliant: RoHS Compliant
C811 C812 = CAP: CAP - CERAMIC,  0.1UF 0402 25VDC Y5V; AGILE_LINK: http://sj-agile9app/Agile/PLMServlet?action=OpenEmailObject&classid=10000&objid=213459527; Item Num: P03-15057R; LIFECYCLE_PHASE: Active; Lead Free Status: Lead Free; MFR_LIFECYCLE: Active; Manufacturer: Murata; Manufacturer Part Num: GRM155F51E104ZA01D; Num Pins: 2; PART_SUBCLASS: CAPACITORS; Part Class: CAPACITORS; RATED_VOLTAGE: 25V; RoHS Compliant: RoHS Compliant; TOLERANCE: +80%/-20%
D41-D44 = MMBD1205: DIODE - ULT FAST, 100V, 200MA, SOT-23; Item Num: P08-20797R; Manufacturer: Fairchild Semiconductor
D45 = LED: LED - BLUE, VF=3.5V, 0805 SMD; Item Num: P09-21321R; Lead Free Status: No; Manufacturer: Wurth; Manufacturer Part Num: 150080BS75000; Num Pins: 2; Part Class: LEDS; RoHS Compliant: Yes
J26 = 2X4_PCIE_ATX: CONN - PCIE ATX, 8POS HEADER, 4.2MM, R/A; Item Num: P23-38586R; Manufacturer: Zhongxlang Electron Science Co. LTD; Manufacturer Part Num: ZES_C-01-0014_8POS_RA
J27 = PCIe_2x3_ATX_0: CONN HEADER 6POS 4.2MM R/A TIN; Item Num: P23-38760R; Manufacturer: Molex; Manufacturer Part Num: 455580003; Manufacturer Part Number: 455580003
R327 R333 R340 = RESISTOR: RES - 5.49M OHM, 1/16W, 1%, 0402 SMD; Item Num: P02-17605R; Lead Free Status: Yes; Manufacturer: Vishay; Manufacturer Part Num: CRCW04025M49FKED; Num Pins: 2; Part Class: Resistors
R328 R334 R341 = RESISTOR: RES,100K OHMS,1.0%,1/16W,0402; Item Num: P02-11386R; Lead Free Status: No; Manufacturer: Panasonic; Manufacturer Part Num: ERJ-2RKF1003X; Num Pins: 2; Part Class: Resistors; Price: 0; RoHS Compliant: Yes
R329 R335 R342 = RES: RES - 200K OHM, 1/16W, 1%, 0402 SMD; Item Num: P02-15992R; Manufacturer: Panasonic; Manufacturer Part Num: ERJ-2RKF2003X; Package: SMD; Part Class: RESISTORS; Type: Resistor
R339 R369 = RESISTOR: RES,1.00K OHMS,1.0%,1/16W,0402; Item Num: P02-11372R; Lead Free Status: No; Manufacturer: Panasonic; Manufacturer Part Num: ERJ-2RKF1001X; Num Pins: 2; Part Class: Resistors
R598 R600 R602 R606 R615 = RESISTOR: RES,60.4K,1/16W,1%,0402,SMD; Item Num: P02-15467R; Manufacturer: Rohm; Manufacturer Part Num: MCR01MZPF6042
R393 R599 R601 R603 R616 = RESISTOR: RES 20.0K OHM 1/16W 1% 0402 SMD; Item Num: P02-14071R; Lead Free Status: Yes; Manufacturer: Panasonic; Manufacturer Part Num: ERJ-2RKF2002X; Num Pins: 2; Part Class: RESISTORS; RoHS Compliant: Yes
R607 = RESISTOR: RES - 23.2K OHM, 1/16W, 1%, 0402 SMD; Item Num: P02-15994R; Lead Free Status: Yes; Manufacturer: Panasonic; Manufacturer Part Num: ERJ-2RKF2322X; Num Pins: 2; Part Class: RESISTORS; RoHS Compliant: Yes
R366-R368 R378 R395 R400 R401 R407 R410 R413 R5310 = RESISTOR: RES ZERO OHM 1/16W 5% 0402 SMD; Altera Part No.: P02-14020R; Item Num: P02-14020R; Lead Free Status: No; Manufacturer: Panasonic; Manufacturer Part Num: ERJ-2GE0R00X; Num Pins: 2; Part Class: RESISTORS; Price: 0; RoHS Compliant: Yes; Tolerance: 5%
R377 R379 R388 R394 R397 R402-R404 R406 R408 R411 R415 R5311 = RESISTOR: RES ZERO OHM 1/16W 5% 0402 SMD; Altera Part No.: P02-14020R; Item Num: P02-14020R; Lead Free Status: No; Manufacturer: Panasonic; Manufacturer Part Num: ERJ-2GE0R00X; Num Pins: 2; Part Class: RESISTORS; RoHS Compliant: Yes; Tolerance: 5%
SW7 = SW_SLIDE_DPDT: SWITCH - SLIDE DPDT, 30V, 0.2AMP, Vertical; Item Num: P11-24518R; Manufacturer: E-SWITCH
U41 U44 U47 U51 U52 = LTC4357: IC - POSITIVE HIGH VOLTAGE IDEAL DIODE CONTROLLER, VIN 9V-80V, 6-LEAD DFN; AGILE_LINK: http://sj-agile9app/Agile/PLMServlet?action=OpenEmailObject&classid=10000&objid=259478351; Item Num: P01-14904R; LIFECYCLE_PHASE: Preliminary; Lead Free Status: Lead Free; MFR_LIFECYCLE: Active; Manufacturer: Linear Technology; Manufacturer Part Num: LTC4357IDCB#xxxPBF; Num Pins: 7; PART_SUBCLASS: ICS; RoHS Compliant: RoHS Compliant
U79 U80 = Single_2-input_AND-Gate: IC GATE AND SGL CMOS 2IN 5TSOP; Item Num: P01-17902R; Manufacturer: On-Semi; Manufacturer Part Num: MC74VHC1G08DTT1G
C347 C348 C362 C364 C378 C384 = CAP: CAP - CER 4700PF 50V 10% X7R 0402; AGILE_LINK: http://sj-agile9app/Agile/PLMServlet?action=OpenEmailObject&classid=10000&objid=215384813; CAPACITANCE: 4.7nF; Item Num: P03-15074R; LIFECYCLE_PHASE: Active; Lead Free Status: Lead Free; MFR_LIFECYCLE: Active; Manufacturer: Murata; Manufacturer Part Num: GRM155R71H472KA01D; Num Pins: 2; PACKAGING: Tape & Reel (TR); PART_SUBCLASS: CAPACITORS; RATED_VOLTAGE: 50V; RoHS Compliant: RoHS Compliant; Supplier Part Num: GRM155R71H472KA01D; Tolerance: +/-10%
C350-C355 C371-C374 C385-C388 = CAP: CAP - CER, 10UF, +/-10%, 35V, X5R, 1210; Dielectric: X5R; Item Num: P03-15992R; Manufacturer: Taiyo Yuden; Manufacturer Part Num: GMK325BJ106KN-T; RATED_VOLTAGE: 35V; RoHS Compliant: Yes; Tolerance: 10%; Working Voltage: 35V
C356-C359 C367-C370 C375 C376 C381 C382 C389 C390 C394 C395 C854-C857 = CAP: CAP - CER 100UF 6.3V X5R 1206; Dielectric: X5R; Item Num: P03-15292R; Manufacturer: Murata; Manufacturer Part Num: GRM31CR60J107ME39L; RATED_VOLTAGE: 6.3v; RoHS Compliant: Yes; Tolerance: 20%; Working Voltage: 6.3V
C360 C361 C365 C366 C377 C383 C391 C396 C848-C853 = PCAP: 470UF(SPCAP EEFCX0D471R , 2V 470UF 15MOHM 2-TERMINAL  ); AGILE_LINK: http://sj-agile9app/Agile/PLMServlet?action=OpenEmailObject&classid=10000&objid=257237054; Item Num: P03-17760R; LIFECYCLE_PHASE: Active; Lead Free Status: Lead Free; MFR_LIFECYCLE: Active; Manufacturer: Panasonic; Manufacturer Part Num: EEFCX0D471R; Num Pins: 2; PART_SUBCLASS: CAPACITORS; RATED_VOLTAGE: 2V; RoHS Compliant: RoHS Compliant; TOLERANCE: +/-20%
C363 = CAP: CAP - CER 4700PF 50V 10% X7R 0402; AGILE_LINK: http://sj-agile9app/Agile/PLMServlet?action=OpenEmailObject&classid=10000&objid=215384813; Item Num: P03-15074R; LIFECYCLE_PHASE: Active; Lead Free Status: Lead Free; MFR_LIFECYCLE: Active; Manufacturer: Murata; Manufacturer Part Num: GRM155R71H472KA01D; Num Pins: 2; PACKAGING: Tape & Reel (TR); PART_SUBCLASS: CAPACITORS; RATED_VOLTAGE: 50V; RoHS Compliant: RoHS Compliant; Supplier Part Num: GRM155R71H472KA01D; Tolerance: +/-10%
Q29 = SI1403DL: MOSFET P-CH 20V 1.6A SOT-363; Item Num: P18-31470R; Manufacturer: Vishay Siliconix; Manufacturer Part Num: SI1403CDL-T1-GE3
R365 = RESISTOR: RES - 2.49K OHM, 1/10W, 1%, 0402, SMD; Item Num: P02-16549R; LIFECYCLE_PHASE: Active; Lead Free Status: No; MFR_LIFECYCLE: Active; Manufacturer: Panasonic; Manufacturer Part Num: ERJ-2RKF2491x; Num Pins: 2; PART_SUBCLASS: RESISTORS; POWER: 1/10W; RESISTANCE: 2.49K; RoHS Compliant: Yes; TOLERANCE: +/-1%
R370 R371 R375 = RESISTOR: RES,10.0K OHMS,1.0%,1/16W, 0402; AGILE_LINK: http://sj-agile9app/Agile/PLMServlet?action=OpenEmailObject&classid=10000&objid=146548997; Item Num: P02-11364R; LIFECYCLE_PHASE: Active; Lead Free Status: No; MFR_LIFECYCLE: Active; Manufacturer: Panasonic; Manufacturer Part Num: ERJ-2RKF1002X; Num Pins: 2; PART_SUBCLASS: RESISTORS; POWER: 1/16W; RoHS Compliant: Yes; TOLERANCE: +/-1%
R372 = RESISTOR: RES - 2.49K OHM, 1/10W, 1%, 0402, SMD; Item Num: P02-16549R; LIFECYCLE_PHASE: Active; Lead Free Status: No; MFR_LIFECYCLE: Active; Manufacturer: Panasonic; Manufacturer Part Num: ERJ-2RKF2491x; Num Pins: 2; PART_SUBCLASS: RESISTORS; POWER: 1/10W; RoHS Compliant: Yes; TOLERANCE: +/-1%
R373 R374 R376 = RESISTOR: RES,10.0K OHMS,1.0%,1/16W, 0402; AGILE_LINK: http://sj-agile9app/Agile/PLMServlet?action=OpenEmailObject&classid=10000&objid=146548997; Item Num: P02-11364R; LIFECYCLE_PHASE: Active; Lead Free Status: No; MFR_LIFECYCLE: Active; Manufacturer: Panasonic; Manufacturer Part Num: ERJ-2RKF1002X; Num Pins: 2; PART_SUBCLASS: RESISTORS; POWER: 1/16W; RESISTANCE: 10.0K; RoHS Compliant: Yes; TOLERANCE: +/-1%
R380 R387 = RESISTOR: RES, 10 OHM, 1%, 1/16W, 0402; Item Num: P02-11651R; Lead Free Status: Yes; Manufacturer: Panasonic; Manufacturer Part Num: ERJ-2RKF10R0X; Num Pins: 2; Part Class: Resistors; Price: 0
R381-R386 = RESISTOR: RES 22.6K OHM 1/16W 1% 0402 SMD; Item Num: P02-16748R; Lead Free Status: No; Manufacturer: Vishay; Manufacturer Part Num: CRCW040222K6FKED; Num Pins: 2; Part Class: Resistors; Price: 0
R619 = RESISTOR: RES - 150K OHMS, 1.0%, 1/16W, 0402; Item Num: P02-15627R; Lead Free Status: Yes; Manufacturer: Panasonic; Manufacturer Part Num: ERJ-2RKF1503x; Num Pins: 2; Part Class: Resistors; Price: 0
R620 = RESISTOR: RES 49.9K OHM 1/16W 1% 0402 SMD; Item Num: P02-15867R; Lead Free Status: Yes; Manufacturer: Panasonic; Manufacturer Part Num: ERJ-2RKF4992X; Num Pins: 2; Part Class: Resistors; Price: 0
U62 = LTC3880-M0001_0: DUAL 18A OR SINGLE 36A UMODULE REGULATOR WITH DIGITAL POWER SYSTEM MANAGEMENT; Component: IC; Item Num: P05-18762R; Manufacturer: Linear Technology; Manufacturer Part Num: LTM4677EY#PBF; Manufacturer Part Number: LTM4677EY#PBF; Vendor: LTC; Vendor P/N: LTC3880_M0001
V13-V15 V17-V29 V62 = VIA_1
C379 C392 = CAP: CAP, CERAMIC, 2.2UF, 10%, 10VDC, X5R, 0603; AGILE_LINK: http://sj-agile9app/Agile/PLMServlet?action=OpenEmailObject&classid=10000&objid=256999866; Item Num: P03-15213R; LIFECYCLE_PHASE: Active; Lead Free Status: Lead Free; MFR_LIFECYCLE: Active; Manufacturer: Murata; Manufacturer Part Num: GRM188R61A225KE34x; Num Pins: 2; PART_SUBCLASS: CAPACITORS; RATED_VOLTAGE: 10V; RoHS Compliant: RoHS Compliant; Supplier Part Num: 490-1545-1-ND; TOLERANCE: +/-10%
C380 C393 = CAP: CAP - CER, 1UF, 10V, +/-10%, X5R, 0402; AGILE_LINK: http://sj-agile9app/Agile/PLMServlet?action=OpenEmailObject&classid=10000&objid=256999866; Item Num: P03-15479R; LIFECYCLE_PHASE: Active; Lead Free Status: Lead Free; MFR_LIFECYCLE: Active; Manufacturer: Murata; Manufacturer Part Num: GRM155R61A105KE15D; Num Pins: 2; PART_SUBCLASS: CAPACITORS; RATED_VOLTAGE: 10V; RoHS Compliant: RoHS Compliant; TOLERANCE: +/-10%
Q2 = PWRMOSFET_EN_GSD: MOSFET N-CH, 60V, 280MA SOT-23; AGILE_LINK: http://sj-agile9app/Agile/PLMServlet?action=OpenEmailObject&classid=10000&objid=258144052; Item Num: P18-31115R; LIFECYCLE_PHASE: Active; Lead Free Status: Lead Free; MFR_LIFECYCLE: Active; Manufacturer: Fairchild Semiconductor; Num Pins: 3; PART_SUBCLASS: MOSFETS; RoHS Compliant: RoHS Compliant
R389 R412 = RESISTOR: RES,121K,1%,1/16W,0402; Item Num: P02-17288R; Lead Free Status: No; Manufacturer: Vishay; Manufacturer Part Num: CRCW0402121KFKED; Mfr Prt #: CRCW0402121KFKED; Num Pins: 2; Part Class: Resistors; Price: 0; RoHS Compliant: Yes; Tolerance: 1%
R390 = RES_16.5K_OHM_1_10W_1%_0402: RES - 60.4K OHM, 1/16W, 1%, 0402, SMD; Item Num: P02-17461R; Manufacturer Part Num: ERJ-2RKF6042X
R391 = RES: RES - 100K OHM, 1/16W, 1%, 0402 SMD; Item Num: P02-17129R; Manufacturer: Rohm Electronics; Manufacturer Part Num: MCR01MZPF1003; Package: SMD; Part Class: RESISTORS; Type: Resistor
R392 = RESISTOR: RES,8.25K OHMS,1.0%,1/16W,0402; Item Num: P02-11425R; Lead Free Status: No; Manufacturer: Panasonic; Manufacturer Part Num: ERJ-2RKF8251X; Num Pins: 2; Part Class: Resistors; Price: 0; RoHS Compliant: Yes; Tolerance: 1%
R396 R414 = RESISTOR: RES, 80.6K OHMS, 1%, 1/16W, 0402; AGILE_LINK: http://sj-agile9app/Agile/PLMServlet?action=OpenEmailObject&classid=10000&objid=14602120; Item Num: P02-14115R; LIFECYCLE_PHASE: Active; Lead Free Status: Lead Free; MFR_LIFECYCLE: Active; Manufacturer: Panasonic; Manufacturer Part Num: ERJ-2RKF8062X; Num Pins: 2; PART_SUBCLASS: RESISTORS; POWER: 1/16W; RoHS Compliant: RoHS Compliant; TOLERANCE: +/-1%; UNIT_PRICE: 0.0076
R398 R399 = RESISTOR: RES,200 OHMS,1.0%,1/16W,0402; Item Num: P02-10716R; Lead Free Status: Yes; Manufacturer: Panasonic; Manufacturer Part Num: ERJ-2RKF2000X; Num Pins: 2; Part Class: Resistors; Price: 0; RoHS Compliant: Yes
R405 = RESISTOR: RES 2.0K OHM 1/16W 1% 0402 SMD; Item Num: P02-16968R; Lead Free Status: Yes; Manufacturer: Vishay; Manufacturer Part Num: CRCW04022K00FKED; Num Pins: 2; Part Class: RESISTORS; Price: 0; RoHS Compliant: Yes
U63 U65 = LTM4650EV_0: REG DUAL 25A OR SINGLE 50A DC/DC ?MODULE REGULATOR; 5th Part Field: LTM4650EY; Item Num: P05-18766R; Manufacturer: Linear Technology; Manufacturer Part Num: LTM4650EY#PBF; Manufacturer Part Number: LTM4650EY#PBF
U64 = LTC6244HMS8: IC - DUAL/QUAD 80MHZ, 25V/?S LOW POWER RAIL-TO-RAIL INPUT AND OUTPUT PRECISION OP AMPS; Item Num: P01-18050R; Manufacturer: Linear Technology; Manufacturer Part Num: LT1801CMS8#PBF; Manufacturer Part Number: LT1801CMS8#PBF

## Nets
3.3V: C345.1 C346.1 U60.1(S1) U60.2(S2) U60.3(S3) U61.6(VOUT) ; also on sheet 9 17 18 19 23 24 25 27 28 29 30 32
3.3V_REG: C333.1 C334.1 C335.1 C336.1 C815.1 U58.A1(VOUT1_1) U58.A2(VOUT1_2) U58.A3(VOUT1_3) U58.A4(VOUT1_4) U58.A5(VOUT1_5) U58.A8(VOUT2_1) U58.A9(VOUT2_2) U58.A10(VOUT2_3) U58.A11(VOUT2_4) U58.A12(VOUT2_5) U58.B1(VOUT1_6) U58.B2(VOUT1_7) U58.B3(VOUT1_8) U58.B4(VOUT1_9) U58.B5(VOUT1_10) U58.B8(VOUT2_6) U58.B9(VOUT2_7) U58.B10(VOUT2_8) U58.B11(VOUT2_9) U58.B12(VOUT2_10) U58.C1(VOUT1_11) U58.C2(VOUT1_12) U58.C3(VOUT1_13) U58.C4(VOUT1_14) U58.C9(VOUT2_11) U58.C10(VOUT2_12) U58.C11(VOUT2_13) U58.C12(VOUT2_14) U58.E8(DIFFP) U60.5(D) U81.5(D) ; also on sheet 31 41 42 43 44
3.3V_REG_COMP: U58.E6(COMP1) U58.E7(COMP2)
3.3V_REG_FB: C815.2 R352.1 U58.D5(VFB1) U58.D7(VFB2)
3.3V_REG_PWRGD: R349.1 U58.G8(PGOOD2) U58.G9(PGOOD1)
3.3V_REG_TRK: C343.1 U58.D8(TRACK2) U58.E5(TRACK1)
3.3V_STBY: C811.2 C812.2 R606.1 R607.2 U79.5(VCC) U80.5(VCC)
5.0V: R339.2 R398.2 R400.1 R401.1 ; also on sheet 31 43 46
12V: C321.1 C322.1 U53.1(S1) U53.2(S2) U53.3(S3) U54.6(VOUT) ; also on sheet 25 29 32
12V_AUX1: D41.2(CATHODE2) J26.1(12V) J26.2(12V) J26.3(12V) R598.2 U39.1(S1) U39.2(S2) U39.3(S3) U41.2(IN)
12V_AUX2: D43.2(CATHODE2) J27.1(12V) J27.2(12V) J27.3(12V) R600.2 U45.1(S1) U45.2(S2) U45.3(S3) U47.2(IN)
12V_G1: C315.1 C316.1 C349.1 C350.1 C351.1 C352.1 C353.1 C354.1 C355.1 C371.1 C372.1 C373.1 C374.1 C385.1 C386.1 C387.1 C388.1 C860.1 C861.1 C862.1 C863.1 R389.2 R391.1 R412.2 R620.2 U40.1(S1) U40.2(S2) U40.3(S3) U43.6(VOUT) U62.A11(VIN0) U62.A12(VIN0) U62.B11(VIN0) U62.B12(VIN0) U62.C11(VIN0) U62.C12(VIN0) U62.D11(VIN0) U62.D12(VIN0) U62.E12(VIN0) U62.F11(SVIN) U62.F12(SVIN) U62.H12(VIN1) U62.J11(VIN1) U62.J12(VIN1) U62.K11(VIN1) U62.K12(VIN1) U62.L11(VIN1) U62.L12(VIN1) U62.M11(VIN1) U62.M12(VIN1) U63.J2(VIN) U63.J3(VIN) U63.J4(VIN) U63.J9(VIN) U63.J10(VIN) U63.J11(VIN) U63.K2(VIN) U63.K3(VIN) U63.K4(VIN) U63.K9(VIN) U63.K10(VIN) U63.K11(VIN) U63.L2(VIN) U63.L3(VIN) U63.L4(VIN) U63.L5(VIN) U63.L6(VIN) U63.L7(VIN) U63.L8(VIN) U63.L9(VIN) U63.L10(VIN) U63.L11(VIN) U63.M2(VIN) U63.M3(VIN) U63.M4(VIN) U63.M5(VIN) U63.M6(VIN) U63.M7(VIN) U63.M8(VIN) U63.M9(VIN) U63.M10(VIN) U63.M11(VIN) U65.J2(VIN) U65.J3(VIN) U65.J4(VIN) U65.J9(VIN) U65.J10(VIN) U65.J11(VIN) U65.K2(VIN) U65.K3(VIN) U65.K4(VIN) U65.K9(VIN) U65.K10(VIN) U65.K11(VIN) U65.L2(VIN) U65.L3(VIN) U65.L4(VIN) U65.L5(VIN) U65.L6(VIN) U65.L7(VIN) U65.L8(VIN) U65.L9(VIN) U65.L10(VIN) U65.L11(VIN) U65.M2(VIN) U65.M3(VIN) U65.M4(VIN) U65.M5(VIN) U65.M6(VIN) U65.M7(VIN) U65.M8(VIN) U65.M9(VIN) U65.M10(VIN) U65.M11(VIN) ; also on sheet 31 38
12V_G2: C318.1 C319.1 U46.1(S1) U46.2(S2) U46.3(S3) U48.6(VOUT) ; also on sheet 31 39 40 43
12V_GROUP1: R327.1 U39.5(D) U40.5(D) U41.1(OUT) U41.6(VDD) U42.5(D) U43.4(VIN) U44.1(OUT) U44.6(VDD)
12V_GROUP2: D42.2(CATHODE2) D44.2(CATHODE2) R333.1 R615.2 U42.1(S1) U42.2(S2) U42.3(S3) U44.2(IN) U45.5(D) U46.5(D) U47.1(OUT) U47.6(VDD) U48.4(VIN) U50.1(S1) U50.2(S2) U50.3(S3) U52.2(IN)
12V_GROUP3: C325.1 C326.2 C327.2 C328.2 C864.1 C865.1 R340.1 U49.5(D) U50.5(D) U51.1(OUT) U51.6(VDD) U52.1(OUT) U52.6(VDD) U53.5(D) U54.4(VIN) U58.J2(VIN21) U58.J3(VIN22) U58.J4(VIN23) U58.J9(VIN24) U58.J10(VIN25) U58.J11(VIN26) U58.K2(VIN27) U58.K3(VIN28) U58.K4(VIN29) U58.K9(VIN30) U58.K10(VIN31) U58.K11(VIN32) U58.L2(VIN11) U58.L3(VIN12) U58.L4(VIN13) U58.L5(VIN14) U58.L6(VIN15) U58.L7(VIN16) U58.L8(VIN17) U58.L9(VIN18) U58.L10(VIN19) U58.L11(VIN20) U58.M2(VIN1) U58.M3(VIN2) U58.M4(VIN3) U58.M5(VIN4) U58.M6(VIN5) U58.M7(VIN6) U58.M8(VIN7) U58.M9(VIN8) U58.M10(VIN9) U58.M11(VIN10) U61.3(UV) U61.4(VIN) U82.3(UV) U82.4(VIN) ; also on sheet 31 32 46
12V_PCIE_SLOT: R602.2 R606.2 U49.1(S1) U49.2(S2) U49.3(S3) U51.2(IN) ; also on sheet 17
GND: C314.1 C315.2 C316.2 C317.1 C318.2 C319.2 C320.1 C321.2 C322.2 C325.2 C326.1 C327.1 C328.1 C333.2 C334.2 C335.2 C336.2 C341.1 C343.2 C344.1 C345.2 C346.2 C348.1 C349.2 C350.2 C351.2 C352.2 C353.2 C354.2 C355.2 C356.2 C357.2 C358.2 C359.2 C360.2 C361.2 C362.1 C365.2 C366.2 C367.2 C368.2 C369.2 C370.2 C371.2 C372.2 C373.2 C374.2 C375.2 C376.2 C377.2 C378.1 C379.2 C380.1 C381.2 C382.2 C383.2 C384.1 C385.2 C386.2 C387.2 C388.2 C389.2 C390.2 C391.2 C392.2 C393.1 C394.2 C395.2 C396.2 C811.1 C812.1 C818.2 C819.2 C820.1 C848.2 C849.2 C850.2 C851.2 C852.2 C853.2 C854.2 C855.2 C856.2 C857.2 C860.2 C861.2 C862.2 C863.2 C864.2 C865.2 D41.1(CATHODE1) D42.1(CATHODE1) D43.1(CATHODE1) D44.1(CATHODE1) D45.2(CATHODE) J26.4(SENSE1) J26.5(GND) J26.6(SENSE0) J26.7(GND) J26.8(GND) J27.4(GND4) J27.6(GND6) Q2.2(SOURCE) R329.2 R335.2 R342.2 R350.2 R352.2 R365.1 R366.1 R368.1 R372.1 R375.1 R381.1 R382.1 R383.1 R384.1 R385.1 R386.1 R387.1 R392.1 R393.1 R394.2 R396.2 R397.2 R407.2 R409.2 R414.2 R415.2 R599.1 R601.1 R603.1 R607.1 R616.1 R619.1 SW7.1 U43.1(GND) U43.9(GND) U48.1(GND) U48.9(GND) U51.4(GND) U51.7(EP_GND) U54.1(GND) U54.9(GND) U58.A6(GND1) U58.A7(GND2) U58.B6(GND3) U58.B7(GND4) U58.C7(SGND4) U58.D1(GND5) U58.D2(GND6) U58.D3(GND7) U58.D4(GND8) U58.D6(SGND5) U58.D9(GND9) U58.D10(GND10) U58.D11(GND11) U58.D12(GND12) U58.E1(GND13) U58.E2(GND14) U58.E3(GND15) U58.E4(GND16) U58.E9(DIFFN) U58.E10(GND17) U58.E11(GND18) U58.E12(GND19) U58.F1(GND20) U58.F2(GND21) U58.F3(GND54) U58.F4(MODE_PLLIN) U58.F6(SGND2) U58.F7(SGND3) U58.F10(GND53) U58.F11(GND52) U58.F12(GND51) U58.G1(GND50) U58.G3(GND49) U58.G4(PHASMD) U58.G6(SGND6) U58.G7(SGND1) U58.G10(GND48) U58.G12(GND47) U58.H1(GND46) U58.H2(GND45) U58.H3(GND44) U58.H4(GND43) U58.H5(GND42) U58.H6(GND41) U58.H7(GND40) U58.H9(GND39) U58.H10(GND38) U58.H11(GND37) U58.H12(GND36) U58.J1(GND35) U58.J5(GND34) U58.J8(GND33) U58.J12(GND32) U58.K1(GND31) U58.K5(GND30) U58.K6(GND29) U58.K7(GND28) U58.K8(GND27) U58.K12(GND26) U58.L1(GND25) U58.L12(GND24) U58.M1(GND23) U58.M12(GND22) U61.1(GND) U61.2(OV) U61.9(GND) U62.A4(GND) U62.A6(GND) U62.A7(GND) U62.A8(GND) U62.A9(GND) U62.A10(GND) U62.B4(GND) U62.B5(GND) U62.B6(GND) U62.B7(GND) U62.B8(GND) U62.B9(GND) U62.C4(GND) U62.C6(GND) U62.C7(GND) U62.C8(GND) U62.C9(GND) U62.D4(GND) U62.D7(GND) U62.E3(GND) U62.F3(GND) U62.F7(SGND) U62.F8(SGND) U62.F10(GND) U62.G3(GND) U62.G7(SGND) U62.G8(SGND) U62.G10(GND) U62.G11(GND) U62.G12(GND) U62.H3(GND) U62.H10(GND) U62.J4(GND) U62.J10(GND) U62.K4(GND) U62.K7(GND) U62.K8(GND) U62.K9(GND) U62.L4(GND) U62.L5(GND) U62.L6(GND) U62.L7(GND) U62.L8(GND) U62.L9(GND) U62.M4(GND) U62.M6(GND) U62.M7(GND) U62.M8(GND) U62.M9(GND) U62.M10(GND) U63.A6(GND) U63.A7(GND) U63.B6(GND) U63.B7(GND) U63.C7(SGND) U63.D1(GND) U63.D2(GND) U63.D3(GND) U63.D4(GND) U63.D6(SGND) U63.D9(GND) U63.D10(GND) U63.D11(GND) U63.D12(GND) U63.E1(GND) U63.E2(GND) U63.E3(GND) U63.E4(GND) U63.E8(DIFFP) U63.E10(GND) U63.E11(GND) U63.E12(GND) U63.F1(GND) U63.F2(GND) U63.F3(GND) U63.F6(SGND) U63.F7(SGND) U63.F10(GND) U63.F11(GND) U63.F12(GND) U63.G1(GND) U63.G3(GND) U63.G6(SGND) U63.G7(SGND) U63.G10(GND) U63.G12(GND) U63.H1(GND) U63.H2(GND) U63.H3(GND) U63.H4(GND) U63.H5(GND) U63.H6(GND) U63.H7(GND) U63.H9(GND) U63.H10(GND) U63.H11(GND) U63.H12(GND) U63.J1(GND) U63.J5(GND) U63.J8(GND) U63.J12(GND) U63.K1(GND) U63.K5(GND) U63.K6(GND) U63.K7(GND) U63.K8(GND) U63.K12(GND) U63.L1(GND) U63.L12(GND) U63.M1(GND) U63.M12(GND) U64.4(V-) U65.A6(GND) U65.A7(GND) U65.B6(GND) U65.B7(GND) U65.C7(SGND) U65.D1(GND) U65.D2(GND) U65.D3(GND) U65.D4(GND) U65.D6(SGND) U65.D9(GND) U65.D10(GND) U65.D11(GND) U65.D12(GND) U65.E1(GND) U65.E2(GND) U65.E3(GND) U65.E4(GND) U65.E8(DIFFP) U65.E10(GND) U65.E11(GND) U65.E12(GND) U65.F1(GND) U65.F2(GND) U65.F3(GND) U65.F6(SGND) U65.F7(SGND) U65.F10(GND) U65.F11(GND) U65.F12(GND) U65.G1(GND) U65.G3(GND) U65.G6(SGND) U65.G7(SGND) U65.G10(GND) U65.G12(GND) U65.H1(GND) U65.H2(GND) U65.H3(GND) U65.H4(GND) U65.H5(GND) U65.H6(GND) U65.H7(GND) U65.H9(GND) U65.H10(GND) U65.H11(GND) U65.H12(GND) U65.J1(GND) U65.J5(GND) U65.J8(GND) U65.J12(GND) U65.K1(GND) U65.K5(GND) U65.K6(GND) U65.K7(GND) U65.K8(GND) U65.K12(GND) U65.L1(GND) U65.L12(GND) U65.M1(GND) U65.M12(GND) U79.3(GND) U80.3(GND) U82.1(GND) U82.2(OV) U82.9(GND) ; also on sheet 6 7 8 9 10 11 12 13 14 15 16 17 18 19 20 21 23 24 25 27 28 29 30 31 32 38 39 40 41 42 43 44 45 46
VCC_ALERTn: R371.2 U62.E5(~{ALERT}) ; also on sheet 6
ATX_PS_ON: J27.5(SNS0) SW7.2
EN_3.3V_REG: U58.F5(RUN1) U58.F9(RUN2) ; also on sheet 31
EN_5V_3.3V: U61.8(~{SHDN}) ; also on sheet 31 43 46
EN_12V_G1: R5310.2 ; also on sheet 31
EN_12V_G2: U48.8(~{SHDN}) ; also on sheet 31
EN_MAX10_VCCONE: U82.8(~{SHDN}) ; also on sheet 31
EN_S10_VCC: R376.2 R379.2 U62.F5(RUN0) ; also on sheet 31
EN_S10_VCCIO_FMCA: U54.8(~{SHDN}) ; also on sheet 31 41 46
LT_ISOLATED_3p3V: Q29.1(D1) Q29.2(D2) Q29.5(D5) Q29.6(D6) ; also on sheet 31
LT_SCL: U62.E6(SCL) ; also on sheet 6 31
LT_SDA: U62.D6(SDA) ; also on sheet 6 31
LTM4650_1_EXTVCC: C380.2 R400.2 U63.J7(EXTVCC)
LTM4650_1_FSET: R396.1 U63.C6(FSET)
LTM4650_1_INTVCC: C379.1 R390.2 R395.1 R399.2 U63.E9(DIFFN) U63.H8(INTVCC)
LTM4650_1_SYNC: R411.1 U63.G5(CLKOUT)
LTM4650_2_EXTVCC: C393.2 U65.J7(EXTVCC)
LTM4650_2_FSET: R414.1 U65.C6(FSET)
LTM4650_2_INTVCC: C392.1 R413.1 U65.E9(DIFFN) U65.H8(INTVCC)
LTM4650_2_SYNC: U65.G5(CLKOUT) V62.1(TP)
LTM4650_COMP: U63.E6(COMP1) U63.E7(COMP2) U64.6(6_-IN_B) U64.7(7_OUT_B) U65.E6(COMP1) U65.E7(COMP2)
LTM4650_RUN: R391.2 R393.2 U63.F5(RUN1) U63.F9(RUN2) U65.F5(RUN1) U65.F9(RUN2)
LTM4650_TRACK: R394.1 U63.D8(TRACK2) U63.E5(TRACK1) U65.D8(TRACK2) U65.E5(TRACK1)
LTM4650_VFB: C378.2 R390.1 R392.2 U63.D5(VFB1) U63.D7(VFB2) U65.D5(VFB1) U65.D7(VFB2)
LTM4677_ASEL: R381.2 U62.G4(ASEL)
LTM4677_CLKOUT: Q2.3(DRAIN) R388.1 R398.1 R399.1
LTM4677_COMP: C347.2 C348.2 C362.2 C363.2 R367.2 R378.1 R406.1 R408.1 U62.E8(COMP0a) U62.H8(COMP1a)
LTM4677_FSWPHCFG: R382.2 U62.H4(FSWPHCFG)
LTM4677_GPIO0: R373.2 R377.1 R408.2 R410.1 U62.E4(~{GPIO0})
LTM4677_GPIO1: R374.2 R377.2 U62.F4(~{GPIO1})
LTM4677_INTVCC: R403.1 U62.F9(INTVCC) U62.G9(INTVCC)
LTM4677_SHARE_CLK: R370.2 U62.H7(SHARE_CLK)
LTM4677_SYNC: Q2.1(GATE) R369.1 U62.E7(SYNC)
LTM4677_VDD33: Q29.4(S) R369.2 R370.1 R371.1 R373.1 R374.1 R376.1 U62.J7(VDD33) V14.1(TP)
LTM4677_VOUT0CFG: R383.2 U62.G5(VOUT0CFG)
LTM4677_VOUT1CFG: R385.2 U62.G6(VOUT1CFG)
LTM4677_VTRIM0CFG: R384.2 U62.H5(VTRIM0CFG)
LTM4677_VTRIM1CFG: R386.2 U62.H6(VTRIM1CFG)
LTM4677_WP: R375.2 U62.K6(WP)
MAX10_VCCONE: C818.1 C819.1 U81.1(S1) U81.2(S2) U81.3(S3) U82.6(VOUT) ; also on sheet 30 31
POWER_EN: R616.2 R5311.1 SW7.5 U80.4(Y) ; also on sheet 31
S10_VCC: C356.1 C357.1 C358.1 C359.1 C360.1 C361.1 C365.1 C366.1 C367.1 C368.1 C369.1 C370.1 C375.1 C376.1 C377.1 C381.1 C382.1 C383.1 C389.1 C390.1 C391.1 C394.1 C395.1 C396.1 C848.1 C849.1 C850.1 C851.1 C852.1 C853.1 C854.1 C855.1 C856.1 C857.1 R380.2 U62.A1(VOUT0) U62.A2(VOUT0) U62.A3(VOUT0) U62.B1(VOUT0) U62.B2(VOUT0) U62.B3(VOUT0) U62.C1(VOUT0) U62.C2(VOUT0) U62.C3(VOUT0) U62.D1(VOUT0) U62.D2(VOUT0) U62.D3(VOUT0) U62.J1(VOUT1) U62.J2(VOUT1) U62.J3(VOUT1) U62.K1(VOUT1) U62.K2(VOUT1) U62.K3(VOUT1) U62.L1(VOUT1) U62.L2(VOUT1) U62.L3(VOUT1) U62.M1(VOUT1) U62.M2(VOUT1) U62.M3(VOUT1) U63.A1(VOUT1) U63.A2(VOUT1) U63.A3(VOUT1) U63.A4(VOUT1) U63.A5(VOUT1) U63.A8(VOUT2) U63.A9(VOUT2) U63.A10(VOUT2) U63.A11(VOUT2) U63.A12(VOUT2) U63.B1(VOUT1) U63.B2(VOUT1) U63.B3(VOUT1) U63.B4(VOUT1) U63.B5(VOUT1) U63.B8(VOUT2) U63.B9(VOUT2) U63.B10(VOUT2) U63.B11(VOUT2) U63.B12(VOUT2) U63.C1(VOUT1) U63.C2(VOUT1) U63.C3(VOUT1) U63.C4(VOUT1) U63.C9(VOUT2) U63.C10(VOUT2) U63.C11(VOUT2) U63.C12(VOUT2) U65.A1(VOUT1) U65.A2(VOUT1) U65.A3(VOUT1) U65.A4(VOUT1) U65.A5(VOUT1) U65.A8(VOUT2) U65.A9(VOUT2) U65.A10(VOUT2) U65.A11(VOUT2) U65.A12(VOUT2) U65.B1(VOUT1) U65.B2(VOUT1) U65.B3(VOUT1) U65.B4(VOUT1) U65.B5(VOUT1) U65.B8(VOUT2) U65.B9(VOUT2) U65.B10(VOUT2) U65.B11(VOUT2) U65.B12(VOUT2) U65.C1(VOUT1) U65.C2(VOUT1) U65.C3(VOUT1) U65.C4(VOUT1) U65.C9(VOUT2) U65.C10(VOUT2) U65.C11(VOUT2) U65.C12(VOUT2) V21.1(TP) V22.1(TP) V24.1(TP) V26.1(TP) V28.1(TP) ; also on sheet 15 16 31 45
S10_VCC_SENSE: C364.2 R380.1 U62.D9(VOSNS0+) U62.H9(VOSNS1) V18.1(TP) ; also on sheet 6 15
S10_VSS_SENSE: C364.1 R387.2 U62.E9(VOSNS0-) ; also on sheet 15
N17122316: C314.2 U40.4(G) U43.5(GATE)
N17122320: R327.2 R328.2 U43.3(UV)
N17122465: R328.1 R329.1 U43.2(OV)
N17126721: U49.4(G) U51.3(GATE)
N17250820: D43.3(ANODE) U47.4(GND) U47.7(EP_GND)
N17250867: U45.4(G) U47.3(GATE)
N17470102: U62.L10(SW1) V13.1(TP)
N17470125: R366.2 U62.M5(SNUB1)
N17470137: U62.G1(ISNS1b-) U62.G2(ISNS1a-)
N17470143: U62.H1(ISNS1b+) U62.H2(ISNS1a+)
N17470149: U62.J5(TSNS1a) U62.K5(TSNS1b)
N17470166: C347.1 R365.2
N17470190: R367.1 U62.J8(COMP1b)
N17470210: U62.B10(SW0) V15.1(TP)
N17470219: R368.2 U62.A5(SNUB0)
N17470265: U62.E1(ISNS0b-) U62.E2(ISNS0a-)
N17470283: U62.F1(ISNS0b+) U62.F2(ISNS0a+)
N17470293: U62.C5(TSNS0b) U62.D5(TSNS0a)
N17470303: R378.2 U62.D8(COMP0b)
N17470315: C363.1 R372.2
N17470407: U62.D10(VORB0+) V17.1(TP)
N17470409: U62.E10(VORB0-) V19.1(TP)
N17470959: U62.J6(VDD25) V20.1(TP)
N17470981: R379.1 U62.F6(RUN1)
N17479682: R395.2 R397.1 U63.G4(PHASMD)
N17479965: R389.1 U63.J6(TEMP)
N17480048: R388.2 U63.F4(MODE-PLLIN)
N17480228: U63.G2(SW1) V23.1(TP)
N17480289: R406.2 U64.3(+IN_A)
N17480308: R402.2 R407.1 U64.2(-IN_A)
N17480357: R402.1 R404.2 U64.1(OUTA)
N17480365: R404.1 R405.2
N17480367: R405.1 R409.1 R410.2 U64.5(5_+IN_B)
N17480420: C384.2 R401.2 R403.2 U64.8(8V+)
N17480663: U63.G11(SW2) V25.1(TP)
N17482654: R411.2 U65.F4(MODE-PLLIN)
N17483103: U65.G11(SW2) V29.1(TP)
N17483171: R412.1 U65.J6(TEMP)
N17483450: R413.2 R415.1 U65.G4(PHASMD)
N18487687: C320.2 U53.4(G) U54.5(GATE)
N18487691: R340.2 R341.2 U54.3(UV)
N18487815: R341.1 R342.1 U54.2(OV)
N18798827: D41.3(ANODE) U41.4(GND) U41.7(EP_GND)
N18798878: U39.4(G) U41.3(GATE)
N18801280: C317.2 U46.4(G) U48.5(GATE)
N18801284: R333.2 R334.2 U48.3(UV)
N18801408: R334.1 R335.1 U48.2(OV)
N18807005: C344.2 U60.4(G) U61.5(GATE)
N19022526: C341.2 R349.2 U58.H8(INTVCC)
N19025527: R350.1 U58.C6(FSET)
N19043037: D45.1(ANODE) R339.1
N20975468: U58.C5(VOUTS1) U58.F8(DIFFOUT)
N20999491: D42.3(ANODE) U44.4(GND) U44.7(EP_GND)
N20999527: U42.4(G) U44.3(GATE)
N20999953: D44.3(ANODE) U52.4(GND) U52.7(EP_GND)
N20999993: U50.4(G) U52.3(GATE)
N21075007: R615.1 SW7.4
N21102315: R598.1 R599.2 U79.1(IN_B)
N21102359: U79.4(Y) U80.1(IN_B)
N21102367: R600.1 R601.2 U79.2(IN_A)
N21102389: R602.1 R603.2 U80.2(IN_A)
N21210851: Q29.3(G) R619.2 R620.1
N21214904: C820.2 U81.4(G) U82.5(GATE)
N21717824: R5310.1 R5311.2 U43.8(~{SHDN})
N22138238: U65.G2(SW1) V27.1(TP)

Not connected (* = marked no-connect by the designer): SW7 3* 6*; U41 5(NC)*; U43 7(~{FAULT})*; U44 5(NC)*; U47 5(NC)*; U48 7(~{FAULT})*; U51 5(NC)*; U52 5(NC)*; U54 7(~{FAULT})*; U58 C8(VOUTS2)* G2(SW1)* G5(CLKOUT)* G11(SW2)* J6(TEMP)* J7(EXTVCC)*; U61 7(~{FAULT})*; U62 C10(DNC1)* E11(DNC2)* H11(DNC3)* J9(VORB1)* K10(DNC4)*; U63 C5(VOUTS1)* C8(VOUTS2)* F8(DIFFOUT)* G8(PGOOD2)* G9(PGOOD1)*; U65 C5(VOUTS1)* C8(VOUTS2)* F8(DIFFOUT)* G8(PGOOD2)* G9(PGOOD1)*; U82 7(~{FAULT})*

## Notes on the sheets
sheet 33
- Power - Select Power Input
- H = 1.0mm
  Place on bottom side
- H = 1.0mm
  Place on bottom side
- 150W
- H = 1.0mm
  Place on bottom side
- H = 1.1mm
  Place on bottom side
- 12V ATX INPUT (12.5A)
- Sense0 = GND
  Sense1 = GND
  A 2 x 4 auxiliary power connector must be plugged into the
  card for additional 150W power
- REVERSE VOLTAGE PROTECTION
- H = 1.1mm
  Place on bottom side
- PCIe
  Aux
  Power
- H = 1.0mm
  Place on bottom side
- REVERSE VOLTAGE PROTECTION
- H = 1.0mm
  Place on bottom side
- PCIe Aux2
  or EXT PWR
- H = 1.0mm
  Place on bottom side
- 75W
- H = 1.1mm
  Place on bottom side
- 12V ATX INPUT (6.25A)
- Sense0 = GND
  Sense1 = GND
  A 2 x 4 auxiliary power connector must be plugged into the
  card for additional 150W power
- REVERSE VOLTAGE PROTECTION
- H = 1.1mm
  Place on bottom side
- H = 1.0mm
  Place on bottom side
- REVERSE VOLTAGE PROTECTION
- H = 1.0mm
  Place on bottom side
- 12V
  PCIE
  Slot
  Power
- H = 1.0mm
  Place on bottom side
- 65W
- H = 1.1mm
  Place on bottom side
- H = 1.0mm
  Place on bottom side
- Power On Switch
- When in PCIE Slot, AUX1 and AUX2
  power must be provided to turn on
  board
- (For external power supply)
- ON
- OFF
- POWER LED
sheet 34
- Power - 12V_REG to 3.3V_REG
- connect AGND to
  PGND through a
  single via
- H = 5.01mm
  Place on Top side
sheet 35
- Power - S10 VCC Part 1
- Consider removing some caps.
  Change caps to smaller package like 0603?
- H = 5.01mm
  Place on Top side
- ASEL = OPEN, I2C address = b'1001111' = 4Fh
  ASEL = LOW, I2C address depends on pull down value.
- connect AGND to
  PGND through a
  single via
sheet 36
- Power - S10 VCC Part 2
- H = 5.01mm
  Place on Top side
sheet 37
- Power - S10 VCC Part 3
- H = 5.01mm
  Place on Top side
